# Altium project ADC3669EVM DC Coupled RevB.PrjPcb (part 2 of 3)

## Sheet ADC IO.SchDoc: ADC Input & Clock
size 431 x 279 mm; Date: Not shown in title block; ApprovedBy: Not shown in title block; CheckedBy: Not shown in title block; Author: Not shown in title block; CompanyName: Not shown in title block; Engineer: Not shown in title block; Organization: Not shown in title block; Address1: Not shown in title block; Address2: Not shown in title block; Address3: Not shown in title block; Address4: Not shown in title block; DocumentNumber: 1; Revision: Use project parameter SCH_Rev; SheetNumber: 8; SheetTotal: 17; PageSetup: Record=PageOptions¦CenterHorizontal=True¦CenterVertical=True¦PrintScale=1.00¦XCorrection=1.00¦YCorrection=1.00¦PrintKind=0¦BorderSize=5000000¦LeftOffset=0¦BottomOffset=0¦Orientation=2¦PaperLength=1000¦PaperWidth=1000¦Scale=100¦PaperSource=15¦PrintQuality=600¦MediaType=1¦DitherType=10¦PaperKind=Letter¦PrintScaleMode=1
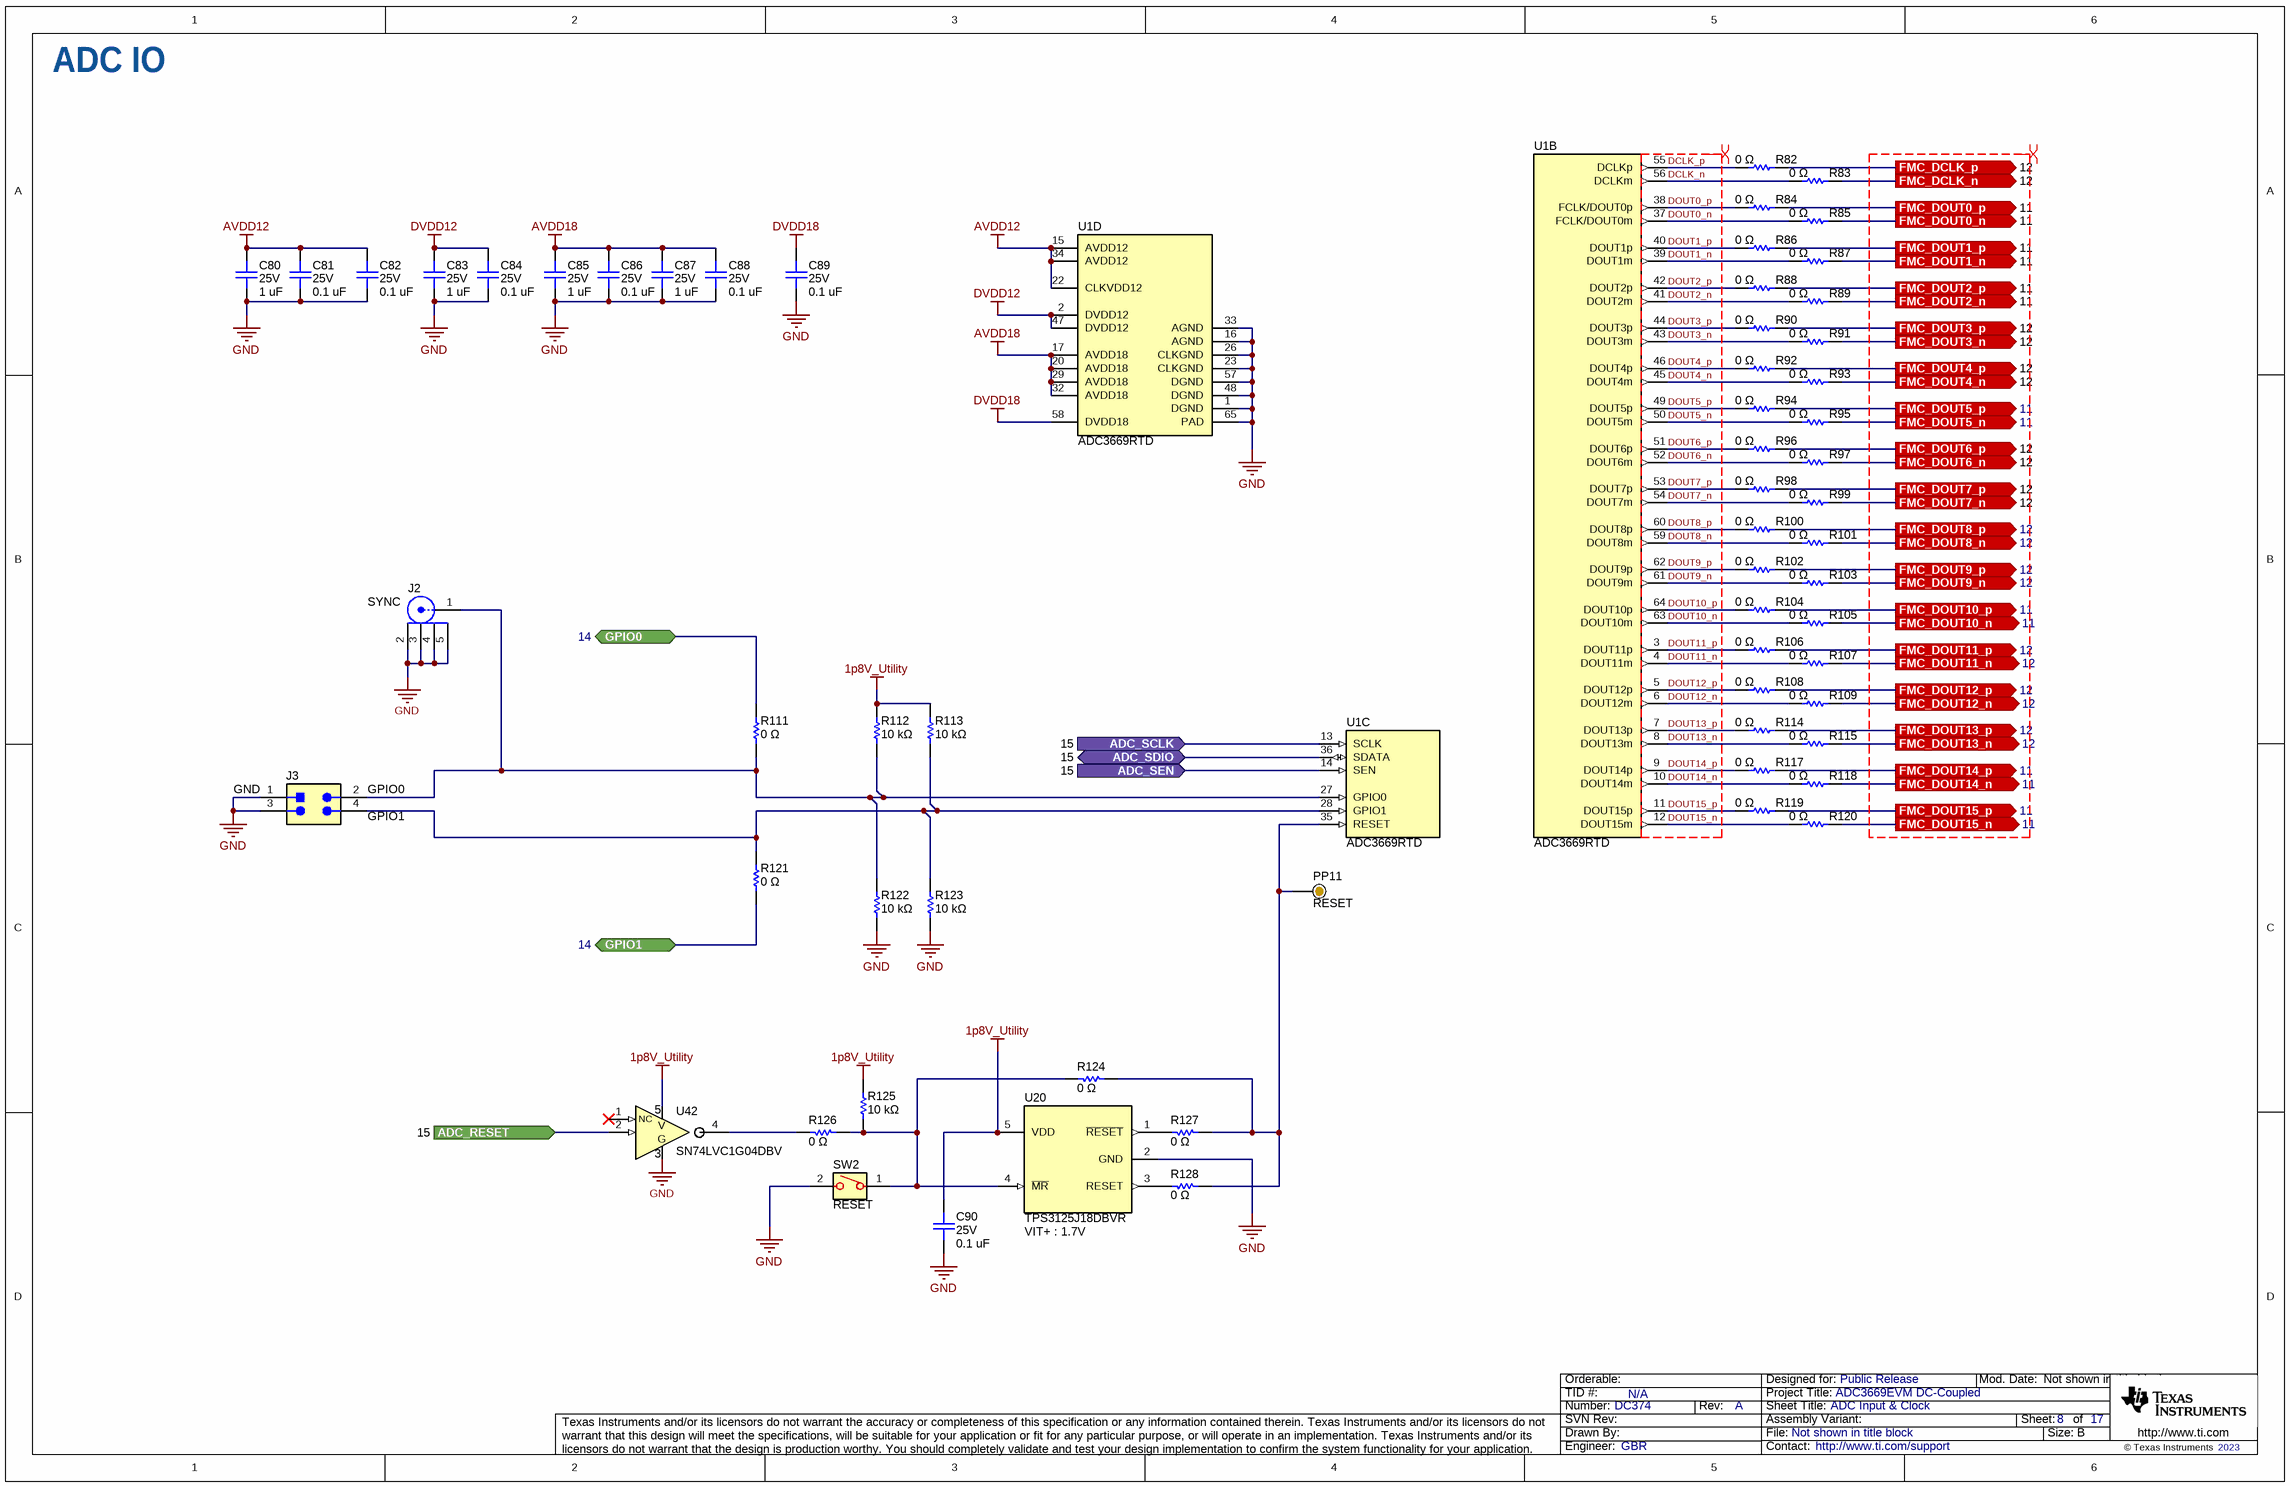
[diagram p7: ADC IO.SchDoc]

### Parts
C80  value 1 uF  Voltage - Rated: 25V  [0402L_cap]  (hidden comment: C1005X5R1E105K050BC)
C81  value 0.1 uF  Voltage - Rated: 25V  [0402L_cap]  (hidden comment: C1005X5R1E104K050BC)
C82  value 0.1 uF  Voltage - Rated: 25V  [0402L_cap]  (hidden comment: C1005X5R1E104K050BC)
C83  value 1 uF  Voltage - Rated: 25V  [0402L_cap]  (hidden comment: C1005X5R1E105K050BC)
C84  value 0.1 uF  Voltage - Rated: 25V  [0402L_cap]  (hidden comment: C1005X5R1E104K050BC)
C85  value 1 uF  Voltage - Rated: 25V  [0402L_cap]  (hidden comment: C1005X5R1E105K050BC)
C86  value 0.1 uF  Voltage - Rated: 25V  [0402L_cap]  (hidden comment: C1005X5R1E104K050BC)
C87  value 1 uF  Voltage - Rated: 25V  [0402L_cap]  (hidden comment: C1005X5R1E105K050BC)
C88  value 0.1 uF  Voltage - Rated: 25V  [0402L_cap]  (hidden comment: C1005X5R1E104K050BC)
C89  value 0.1 uF  Voltage - Rated: 25V  [0402L_cap]  (hidden comment: C1005X5R1E104K050BC)
C90  value 0.1 uF  Voltage - Rated: 25V  [0402L_cap]  (hidden comment: C1005X5R1E104K050BC)
J2  Text1: SYNC  [FP-132134-15_CONN_SMA_JACK-MFG]  (hidden comment: 132134-15)
J3  Text4: GPIO1  Text3: GND  Text2: GPIO0  [PBC02DAAN]  (hidden comment: TSW-102-14-S-D)
PP11  Text1: RESET  [ProbePoint_TH_40mil]  (hidden comment: Probe Point)  (no BOM)
R82  value 0 Ω  [0201]  (hidden comment: ERJ-1GN0R00C)
R83  value 0 Ω  [0201]  (hidden comment: ERJ-1GN0R00C)
R84  value 0 Ω  [0201]  (hidden comment: ERJ-1GN0R00C)
R85  value 0 Ω  [0201]  (hidden comment: ERJ-1GN0R00C)
R86  value 0 Ω  [0201]  (hidden comment: ERJ-1GN0R00C)
R87  value 0 Ω  [0201]  (hidden comment: ERJ-1GN0R00C)
R88  value 0 Ω  [0201]  (hidden comment: ERJ-1GN0R00C)
R89  value 0 Ω  [0201]  (hidden comment: ERJ-1GN0R00C)
R90  value 0 Ω  [0201]  (hidden comment: ERJ-1GN0R00C)
R91  value 0 Ω  [0201]  (hidden comment: ERJ-1GN0R00C)
R92  value 0 Ω  [0201]  (hidden comment: ERJ-1GN0R00C)
R93  value 0 Ω  [0201]  (hidden comment: ERJ-1GN0R00C)
R94  value 0 Ω  [0201]  (hidden comment: ERJ-1GN0R00C)
R95  value 0 Ω  [0201]  (hidden comment: ERJ-1GN0R00C)
R96  value 0 Ω  [0201]  (hidden comment: ERJ-1GN0R00C)
R97  value 0 Ω  [0201]  (hidden comment: ERJ-1GN0R00C)
R98  value 0 Ω  [0201]  (hidden comment: ERJ-1GN0R00C)
R99  value 0 Ω  [0201]  (hidden comment: ERJ-1GN0R00C)
R100  value 0 Ω  [0201]  (hidden comment: ERJ-1GN0R00C)
R101  value 0 Ω  [0201]  (hidden comment: ERJ-1GN0R00C)
R102  value 0 Ω  [0201]  (hidden comment: ERJ-1GN0R00C)
R103  value 0 Ω  [0201]  (hidden comment: ERJ-1GN0R00C)
R104  value 0 Ω  [0201]  (hidden comment: ERJ-1GN0R00C)
R105  value 0 Ω  [0201]  (hidden comment: ERJ-1GN0R00C)
R106  value 0 Ω  [0201]  (hidden comment: ERJ-1GN0R00C)
R107  value 0 Ω  [0201]  (hidden comment: ERJ-1GN0R00C)
R108  value 0 Ω  [0201]  (hidden comment: ERJ-1GN0R00C)
R109  value 0 Ω  [0201]  (hidden comment: ERJ-1GN0R00C)
R111  value 0 Ω  [0402L]  (hidden comment: ERJ-2GE0R00X)
R112  value 10 kΩ  [0402L]  (hidden comment: ERJ-PA2F1002X)
R113  value 10 kΩ  [0402L]  (hidden comment: ERJ-PA2F1002X)
R114  value 0 Ω  [0201]  (hidden comment: ERJ-1GN0R00C)
R115  value 0 Ω  [0201]  (hidden comment: ERJ-1GN0R00C)
R117  value 0 Ω  [0201]  (hidden comment: ERJ-1GN0R00C)
R118  value 0 Ω  [0201]  (hidden comment: ERJ-1GN0R00C)
R119  value 0 Ω  [0201]  (hidden comment: ERJ-1GN0R00C)
R120  value 0 Ω  [0201]  (hidden comment: ERJ-1GN0R00C)
R121  value 0 Ω  [0402L]  (hidden comment: ERJ-2GE0R00X)
R122  value 10 kΩ  [0402L]  (hidden comment: ERJ-PA2F1002X)
R123  value 10 kΩ  [0402L]  (hidden comment: ERJ-PA2F1002X)
R124  value 0 Ω  [0402L]  (hidden comment: ERJ-2GE0R00X)
R125  value 10 kΩ  [0402L]  (hidden comment: ERJ-2RKF1002X)
R126  value 0 Ω  [0402L]  (hidden comment: ERJ-2GE0R00X)
R127  value 0 Ω  [0402L]  (hidden comment: ERJ-2GE0R00X)
R128  value 0 Ω  [0402L]  (hidden comment: ERJ-2GE0R00X)
SW2  Text1: RESET  [FSMSM]  (hidden comment: FSMSM)
U1  ADC3669RTD  [RTD0064L]  (parts B,C,D of 4)
U20  TPS3125J18DBVR  Text1: VIT+ : 1.7V  [DBV0005A]
U42  SN74LVC1G04DBV  [DBV0005A]

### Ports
ADC_RESET (in, see 15), ADC_SCLK (in, see 15), ADC_SDIO (bidir, see 15), ADC_SEN (in, see 15), FMC_DCLK_n (out, see 12), FMC_DCLK_p (out, see 12), FMC_DOUT0_n (out, see 11), FMC_DOUT0_p (out, see 11), FMC_DOUT1_n (out, see 11), FMC_DOUT1_p (out, see 11), FMC_DOUT2_n (out, see 11), FMC_DOUT2_p (out, see 11), FMC_DOUT3_n (out, see 12), FMC_DOUT3_p (out, see 12), FMC_DOUT4_n (out, see 12), FMC_DOUT4_p (out, see 12), FMC_DOUT5_n (out, see 11), FMC_DOUT5_p (out, see 11), FMC_DOUT6_n (out, see 12), FMC_DOUT6_p (out, see 12), FMC_DOUT7_n (out, see 12), FMC_DOUT7_p (out, see 12), FMC_DOUT8_n (out, see 12), FMC_DOUT8_p (out, see 12), FMC_DOUT9_n (out, see 12), FMC_DOUT9_p (out, see 12), FMC_DOUT10_n (out, see 11), FMC_DOUT10_p (out, see 11), FMC_DOUT11_n (out, see 12), FMC_DOUT11_p (out, see 12), FMC_DOUT12_n (out, see 12), FMC_DOUT12_p (out, see 12), FMC_DOUT13_n (out, see 12), FMC_DOUT13_p (out, see 12), FMC_DOUT14_n (out, see 11), FMC_DOUT14_p (out, see 11), FMC_DOUT15_n (out, see 11), FMC_DOUT15_p (out, see 11), GPIO0 (bidir, see 14), GPIO1 (bidir, see 14)

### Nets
1p8V_Utility: C90.2 R112.1 R113.1 R125.2 U20.5(VDD) U42.5(VCC)
AVDD12: C80.2 C81.2 C82.2 U1.15(AVDD12) U1.22(CLKVDD12) U1.34(AVDD12)
AVDD18: C85.2 C86.2 C87.2 C88.2 U1.17(AVDD18) U1.20(AVDD18) U1.29(AVDD18) U1.32(AVDD18)
DVDD12: C83.2 C84.2 U1.2(DVDD12) U1.47(DVDD12)
DVDD18: C89.2 U1.58(DVDD18)
GND: C80.1 C81.1 C82.1 C83.1 C84.1 C85.1 C86.1 C87.1 C88.1 C89.1 C90.1 J2.2 J2.3 J2.4 J2.5 J3.1 J3.3 R122.2 R123.2 SW2.2 U1.1(DGND) U1.16(AGND) U1.23(CLKGND) U1.26(CLKGND) U1.33(AGND) U1.48(DGND) U1.57(DGND) U1.65(PAD) U20.2(GND) U42.3(GND)
ADC_RESET: U42.2(A) ; port ADC_RESET
ADC_SCLK: U1.13(SCLK) ; port ADC_SCLK
ADC_SDIO: U1.36(SDATA) ; port ADC_SDIO
ADC_SEN: U1.14(SEN) ; port ADC_SEN
DCLK_n: R83.1 U1.56(DCLKm)
DCLK_p: R82.1 U1.55(DCLKp)
DOUT0_n: R85.1 U1.37(FCLK/DOUT0m)
DOUT0_p: R84.1 U1.38(FCLK/DOUT0p)
DOUT1_n: R87.1 U1.39(DOUT1m)
DOUT1_p: R86.1 U1.40(DOUT1p)
DOUT2_n: R89.1 U1.41(DOUT2m)
DOUT2_p: R88.1 U1.42(DOUT2p)
DOUT3_n: R91.1 U1.43(DOUT3m)
DOUT3_p: R90.1 U1.44(DOUT3p)
DOUT4_n: R93.1 U1.45(DOUT4m)
DOUT4_p: R92.1 U1.46(DOUT4p)
DOUT5_n: R95.1 U1.50(DOUT5m)
DOUT5_p: R94.1 U1.49(DOUT5p)
DOUT6_n: R97.1 U1.52(DOUT6m)
DOUT6_p: R96.1 U1.51(DOUT6p)
DOUT7_n: R99.1 U1.54(DOUT7m)
DOUT7_p: R98.1 U1.53(DOUT7p)
DOUT8_n: R101.1 U1.59(DOUT8m)
DOUT8_p: R100.1 U1.60(DOUT8p)
DOUT9_n: R103.1 U1.61(DOUT9m)
DOUT9_p: R102.1 U1.62(DOUT9p)
DOUT10_n: R105.1 U1.63(DOUT10m)
DOUT10_p: R104.1 U1.64(DOUT10p)
DOUT11_n: R107.1 U1.4(DOUT11m)
DOUT11_p: R106.1 U1.3(DOUT11p)
DOUT12_n: R109.1 U1.6(DOUT12m)
DOUT12_p: R108.1 U1.5(DOUT12p)
DOUT13_n: R115.1 U1.8(DOUT13m)
DOUT13_p: R114.1 U1.7(DOUT13p)
DOUT14_n: R118.1 U1.10(DOUT14m)
DOUT14_p: R117.1 U1.9(DOUT14p)
DOUT15_n: R120.1 U1.12(DOUT15m)
DOUT15_p: R119.1 U1.11(DOUT15p)
FMC_DCLK_n: R83.2 ; port FMC_DCLK_n
FMC_DCLK_p: R82.2 ; port FMC_DCLK_p
FMC_DOUT0_n: R85.2 ; port FMC_DOUT0_n
FMC_DOUT0_p: R84.2 ; port FMC_DOUT0_p
FMC_DOUT1_n: R87.2 ; port FMC_DOUT1_n
FMC_DOUT1_p: R86.2 ; port FMC_DOUT1_p
FMC_DOUT2_n: R89.2 ; port FMC_DOUT2_n
FMC_DOUT2_p: R88.2 ; port FMC_DOUT2_p
FMC_DOUT3_n: R91.2 ; port FMC_DOUT3_n
FMC_DOUT3_p: R90.2 ; port FMC_DOUT3_p
FMC_DOUT4_n: R93.2 ; port FMC_DOUT4_n
FMC_DOUT4_p: R92.2 ; port FMC_DOUT4_p
FMC_DOUT5_n: R95.2 ; port FMC_DOUT5_n
FMC_DOUT5_p: R94.2 ; port FMC_DOUT5_p
FMC_DOUT6_n: R97.2 ; port FMC_DOUT6_n
FMC_DOUT6_p: R96.2 ; port FMC_DOUT6_p
FMC_DOUT7_n: R99.2 ; port FMC_DOUT7_n
FMC_DOUT7_p: R98.2 ; port FMC_DOUT7_p
FMC_DOUT8_n: R101.2 ; port FMC_DOUT8_n
FMC_DOUT8_p: R100.2 ; port FMC_DOUT8_p
FMC_DOUT9_n: R103.2 ; port FMC_DOUT9_n
FMC_DOUT9_p: R102.2 ; port FMC_DOUT9_p
FMC_DOUT10_n: R105.2 ; port FMC_DOUT10_n
FMC_DOUT10_p: R104.2 ; port FMC_DOUT10_p
FMC_DOUT11_n: R107.2 ; port FMC_DOUT11_n
FMC_DOUT11_p: R106.2 ; port FMC_DOUT11_p
FMC_DOUT12_n: R109.2 ; port FMC_DOUT12_n
FMC_DOUT12_p: R108.2 ; port FMC_DOUT12_p
FMC_DOUT13_n: R115.2 ; port FMC_DOUT13_n
FMC_DOUT13_p: R114.2 ; port FMC_DOUT13_p
FMC_DOUT14_n: R118.2 ; port FMC_DOUT14_n
FMC_DOUT14_p: R117.2 ; port FMC_DOUT14_p
FMC_DOUT15_n: R120.2 ; port FMC_DOUT15_n
FMC_DOUT15_p: R119.2 ; port FMC_DOUT15_p
GPIO0: R111.2 ; port GPIO0
GPIO1: R121.1 ; port GPIO1
NetJ2_1: J2.1 J3.2 R111.1 R112.2 R122.1 U1.27(GPIO0)
NetJ3_4: J3.4 R113.2 R121.2 R123.1 U1.28(GPIO1)
NetPP11_1: PP11.1 R124.1 R127.1 R128.1 U1.35(RESET)
NetR124_2: R124.2 R125.1 R126.1 SW2.1 U20.4(~{MR})
NetR126_2: R126.2 U42.4(Y)
NetR127_2: R127.2 U20.1(~{RESET})
NetR128_2: R128.2 U20.3(RESET)

Not connected (* = marked no-connect by the designer): U42 1(NC)*

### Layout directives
differential pair; net class SERDES: (no net found under the mark)
differential pair: DCLK_n, DCLK_p, DOUT0_n, DOUT0_p, DOUT1_n, DOUT1_p, DOUT2_n, DOUT2_p, DOUT3_n, DOUT3_p, DOUT4_n, DOUT4_p, DOUT5_n, DOUT5_p, DOUT6_n, DOUT6_p, DOUT7_n, DOUT7_p, DOUT8_n, DOUT8_p, DOUT9_n, DOUT9_p, DOUT10_n, DOUT10_p, DOUT11_n, DOUT11_p, DOUT12_n, DOUT12_p, DOUT13_n, DOUT13_p, DOUT14_n, DOUT14_p, DOUT15_n, DOUT15_p

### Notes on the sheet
- ADC IO

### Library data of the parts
C80 C83 C85 C87 = capcc02750: CAP CER 1UF 25V X5R 0402; Manufacturer: TDK Corporation; CompType: Capacitor Ceramic; Tolerance: ±10%; SizeX_mm: 1; SizeY_mm: 0.5; SizeZ_mm: 0.55
C81 C82 C84 C86 C88-C90 = capcc01263: CAP CER 0.1UF 25V X5R 0402; Manufacturer: TDK Corporation; CompType: Capacitor Ceramic; Tolerance: ±10%; SizeX_mm: 1; SizeY_mm: 0.5; SizeZ_mm: 0.55
J2 = 132134-15: SMA Connector Jack, Female Socket 50Ohm Surface Mount, Through Hole Solder; Manufacturer: Amphenol RF; UniqueID: cmp00028; CompType: RF Connector
J3 = TSW-102-14-S-D: Header, 100mil, 2x2, Gold, TH; Manufacturer: Samtec; Alt Manufacturer: Sullins Connector Solutions; UniqueID: cmp00018; Pitch (mm): 2.54
PP11 = cmp00025: Probe Point that can be used in lue of a test point
R82-R109 R114 R115 R117-R120 = RSMD020101699: RES SMD 0 OHM JUMPER 1/20W 0201; Manufacturer: Panasonic Electronic Components; CompType: Resistor SMD; Power (Watts): 0.05W, 1/20W
R111 R121 R124 R126-R128 = RSMD040200001: RES SMD 0 OHM JUMPER 1/10W 0402; Manufacturer: Panasonic Electronic Components; CompType: Resistor SMD; Power (Watts): 0.1W, 1/10W; SizeX_mm: 1; SizeY_mm: 0.5; SizeZ_mm: 0.4
R112 R113 R122 R123 = RSMD040200311: RES SMD 10K OHM 1% 1/5W 0402; Manufacturer: Panasonic Electronic Components; CompType: Resistor SMD; Power (Watts): 0.2W, 1/5W; Temperature Coefficient: ±100ppm/°C; SizeX_mm: 1; SizeY_mm: 0.5; SizeZ_mm: 0.4
R125 = RSMD040200314: RES SMD 10K OHM 1% 1/10W 0402; Manufacturer: Panasonic Electronic Components; CompType: Resistor SMD; Power (Watts): 0.1W, 1/10W; Temperature Coefficient: ±100ppm/°C; SizeX_mm: 1; SizeY_mm: 0.5; SizeZ_mm: 0.4
SW2 = cmp00234: SWITCH TACTILE SPST-NO 0.05A 24V; Manufacturer: TE Connectivity; CompType: Push Button
U1 = cmp00321: 16-Bit 500-MSPS Analog-to-Digital Converter; Manufacturer: Texas Instruments; CompType: ADC
U20 = cmp00229: Push-pull, supply voltage supervisor with manual reset; Manufacturer: Texas Instruments; Alt PartNumber: TPS3125J18DBVT; CompType: Voltage Detector
U42 = SN74LVC1G04DBV: Single 1.65-V to 5.5-V inverter; Manufacturer: Texas Instruments

## Sheet ADC Analog Input.SchDoc
size 431 x 279 mm; Date: Not shown in title block; ApprovedBy: Not shown in title block; CheckedBy: Not shown in title block; Author: Not shown in title block; CompanyName: Not shown in title block; Engineer: Not shown in title block; Organization: Not shown in title block; Address1: Not shown in title block; Address2: Not shown in title block; Address3: Not shown in title block; Address4: Not shown in title block; DocumentNumber: 1; Revision: Use project parameter SCH_Rev; SheetNumber: 9; SheetTotal: 17; PageSetup: Record=PageOptions¦CenterHorizontal=True¦CenterVertical=True¦PrintScale=1.00¦XCorrection=1.00¦YCorrection=1.00¦PrintKind=0¦BorderSize=5000000¦LeftOffset=0¦BottomOffset=0¦Orientation=2¦PaperLength=1000¦PaperWidth=1000¦Scale=100¦PaperSource=15¦PrintQuality=600¦MediaType=1¦DitherType=10¦PaperKind=Letter¦PrintScaleMode=1
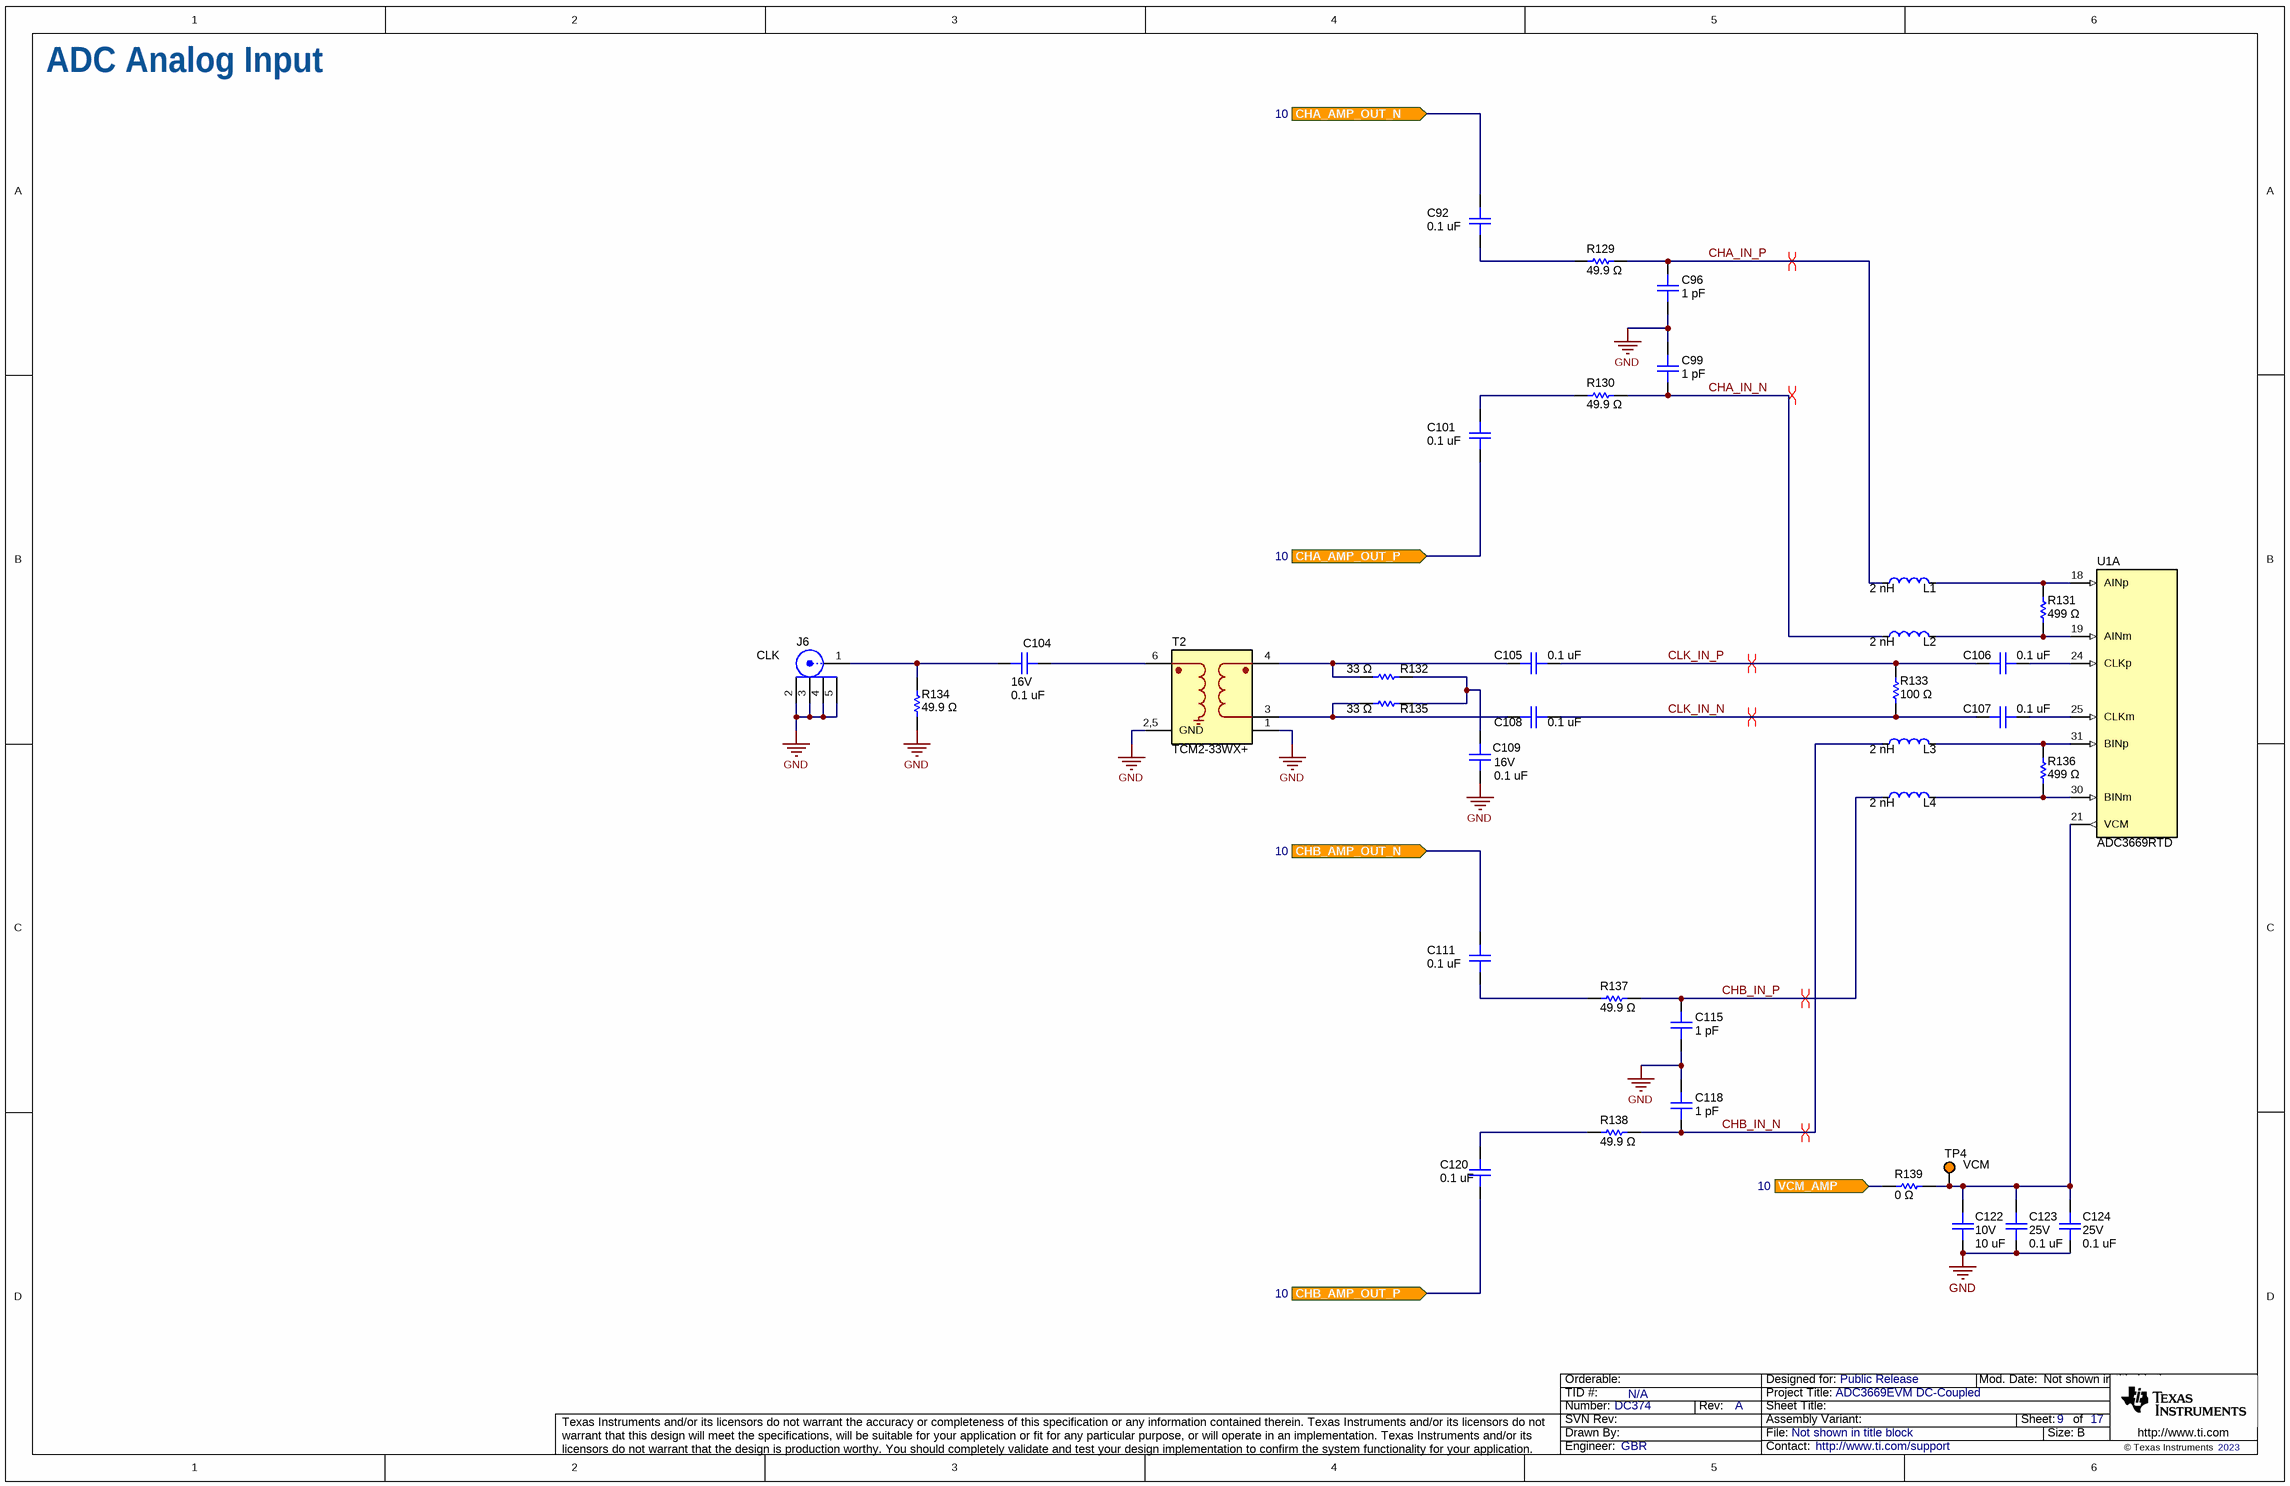
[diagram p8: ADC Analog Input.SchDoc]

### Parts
C92  value 0.1 uF  [0201_cap]  (hidden comment: GRM033Z71C104KE14D)
C96  value 1 pF  [0201_cap]  (hidden comment: 02015J1R0PBSTR)
C99  value 1 pF  [0201_cap]  (hidden comment: 02015J1R0PBSTR)
C101  value 0.1 uF  [0201_cap]  (hidden comment: GRM033Z71C104KE14D)
C104  value 0.1 uF  Voltage - Rated: 16V  [0201_cap]  (hidden comment: GRM033Z71C104KE14D)
C105  value 0.1 uF  [0201_cap]  (hidden comment: GRM033Z71C104KE14D)
C106  value 0.1 uF  [0201_cap]  (hidden comment: GRM033Z71C104KE14D)
C107  value 0.1 uF  [0201_cap]  (hidden comment: GRM033Z71C104KE14D)
C108  value 0.1 uF  [0201_cap]  (hidden comment: GRM033Z71C104KE14D)
C109  value 0.1 uF  Voltage - Rated: 16V  [0201_cap]  (hidden comment: GRM033Z71C104KE14D)
C111  value 0.1 uF  [0201_cap]  (hidden comment: GRM033Z71C104KE14D)
C115  value 1 pF  [0201_cap]  (hidden comment: 02015J1R0PBSTR)
C118  value 1 pF  [0201_cap]  (hidden comment: 02015J1R0PBSTR)
C120  value 0.1 uF  [0201_cap]  (hidden comment: GRM033Z71C104KE14D)
C122  value 10 uF  Voltage - Rated: 10V  [0402L_cap]  (hidden comment: 0402ZD106MAT2A)
C123  value 0.1 uF  Voltage - Rated: 25V  [0402L_cap]  (hidden comment: C1005X5R1E104K050BC)
C124  value 0.1 uF  Voltage - Rated: 25V  [0402L_cap]  (hidden comment: C1005X5R1E104K050BC)
J6  Text1: CLK  [FP-132134-15_CONN_SMA_JACK-MFG]  (hidden comment: 132134-15)
L1  value 2 nH  [0201]  (hidden comment: LQP03HQ2N0B02D)
L2  value 2 nH  [0201]  (hidden comment: LQP03HQ2N0B02D)
L3  value 2 nH  [0201]  (hidden comment: LQP03HQ2N0B02D)
L4  value 2 nH  [0201]  (hidden comment: LQP03HQ2N0B02D)
R129  value 49.9 Ω  [0201]  (hidden comment: ERJ-U01F49R9C)
R130  value 49.9 Ω  [0201]  (hidden comment: ERJ-U01F49R9C)
R131  value 499 Ω  [0201]  (hidden comment: ERJ-1GNF4990C)
R132  value 33 Ω  [0201]  (hidden comment: ERJ-1GNF33R0C)
R133  value 100 Ω  [0201]  (hidden comment: ERJ-1GNF1000C)
R134  value 49.9 Ω  [0201]  (hidden comment: ERJ-U01F49R9C)
R135  value 33 Ω  [0201]  (hidden comment: ERJ-1GNF33R0C)
R136  value 499 Ω  [0201]  (hidden comment: ERJ-1GNF4990C)
R137  value 49.9 Ω  [0201]  (hidden comment: ERJ-U01F49R9C)
R138  value 49.9 Ω  [0201]  (hidden comment: ERJ-U01F49R9C)
R139  value 0 Ω  [0402L]  (hidden comment: ERJ-2GE0R00X)
T2  TCM2-33WX+  [DB1627 - Vias 1,2,5]
TP4  Text1: VCM  [Keystone5013]  (hidden comment: cmp00043)
U1  ADC3669RTD  [RTD0064L]  (part A of 4)

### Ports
CHA_AMP_OUT_N (in, see 10), CHA_AMP_OUT_P (in, see 10), CHB_AMP_OUT_N (in, see 10), CHB_AMP_OUT_P (in, see 10), VCM_AMP (in, see 10)

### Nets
GND: C96.1 C99.2 C109.1 C115.1 C118.2 C122.1 C123.1 C124.1 J6.2 J6.3 J6.4 J6.5 R134.1 T2.1 T2.2,5(GND)
CHA_AMP_OUT_N: C92.1 ; port CHA_AMP_OUT_N
CHA_AMP_OUT_P: C101.2 ; port CHA_AMP_OUT_P
CHA_IN_N: C99.1 L2.1 R130.2
CHA_IN_P: C96.2 L1.1 R129.2
CHB_AMP_OUT_N: C111.2 ; port CHB_AMP_OUT_N
CHB_AMP_OUT_P: C120.1 ; port CHB_AMP_OUT_P
CHB_IN_N: C118.1 L3.1 R138.2
CHB_IN_P: C115.2 L4.1 R137.2
CLK_IN_N: C107.1 C108.2 R133.1
CLK_IN_P: C105.2 C106.1 R133.2
VCM_AMP: R139.2 ; port VCM_AMP
NetC92_2: C92.2 R129.1
NetC101_1: C101.1 R130.1
NetC104_1: C104.1 J6.1 R134.2
NetC104_2: C104.2 T2.6(Primary_Dot)
NetC105_1: C105.1 R132.2 T2.4(Secondary_Dot)
NetC106_2: C106.2 U1.24(CLKp)
NetC107_2: C107.2 U1.25(CLKm)
NetC108_1: C108.1 R135.2 T2.3
NetC109_2: C109.2 R132.1 R135.1
NetC111_1: C111.1 R137.1
NetC120_2: C120.2 R138.1
NetC122_2: C122.2 C123.2 C124.2 R139.1 TP4.1 U1.21(VCM)
NetL1_2: L1.2 R131.2 U1.18(AINp)
NetL2_2: L2.2 R131.1 U1.19(AINm)
NetL3_2: L3.2 R136.2 U1.31(BINp)
NetL4_2: L4.2 R136.1 U1.30(BINm)

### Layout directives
differential pair: CHA_IN_N, CHA_IN_P, CHB_IN_N, CHB_IN_P, CLK_IN_N, CLK_IN_P

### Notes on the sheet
- ADC Analog Input

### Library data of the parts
C92 C101 C104-C109 C111 C120 = capcc09263: CAP CER 0.1UF 16V X7R 0201; Manufacturer: Murata Electronics; SizeZ_mm: 0.33; SizeY_mm: 0.3; CompType: Capacitor Ceramic; SizeX_mm: 0.6; Tolerance: ±10%
C96 C99 C115 C118 = 0201RFCaps0738: CAP THIN FILM 1PF 50V 0201; Manufacturer: KYOCERA AVX; CompType: Capactior RF; Tolerance: ±0.02pF; SizeX_mm: 0.58; SizeY_mm: 0.3; SizeZ_mm: 0.33
C122 = capcc09406: CAP CER 10UF 10V X5R 0402; Manufacturer: KYOCERA AVX; CompType: Capacitor Ceramic; Tolerance: ±20%; SizeX_mm: 1; SizeY_mm: 0.5; SizeZ_mm: 0.7
C123 C124 = capcc01263: as C81 on sheet ADC IO
J6 = 132134-15: as J2 on sheet ADC IO
L1-L4 = indrf00113: FIXED IND 2NH 600MA 120MOHM SMD; Manufacturer: Murata Electronics; CompType: Inductor RF; Tolerance: ±0.1nH; Material: Non-Magnetic; DC Resistance (DCR): 120mOhm Max; Q @ Freq: 20 @ 500MHz; Frequency - Self Resonant: 9GHz; SizeX_mm: 0.76; SizeY_mm: 0.33; SizeZ_mm: 0.55
R129 R130 R134 R137 R138 = RSMD020100423: RES 49.9 OHM 1% 1/20W 0201 SMD; Manufacturer: Panasonic Electronic Components; CompType: Resistor SMD; Power (Watts): 0.05W, 1/20W; Temperature Coefficient: ±200ppm/°C
R131 R136 = RSMD020100201: RES SMD 499 OHM 1% 1/20W 0201; Manufacturer: Panasonic Electronic Components; CompType: Resistor SMD; Power (Watts): 0.05W, 1/20W; Temperature Coefficient: ±200ppm/°C
R132 R135 = RSMD020100013: RES SMD 33 OHM 1% 1/20W 0201; Manufacturer: Panasonic Electronic Components; CompType: Resistor SMD; Power (Watts): 0.05W, 1/20W; Temperature Coefficient: ±200ppm/°C
R133 = RSMD020100289: RES SMD 100 OHM 1% 1/20W 0201; Manufacturer: Panasonic Electronic Components; CompType: Resistor SMD; Power (Watts): 0.05W, 1/20W; Temperature Coefficient: ±200ppm/°C
R139 = RSMD040200001: as R111 on sheet ADC IO
T2 = TCM2-33WX+: 1:2 CORE & WIRE Transformer, 10 to 3000 MHz, 50Ω; Manufacturer: Mini-Circuits; CompType: Balun; UniqueID: cmp00349
TP4 = cmp00043: Test Point, Multipurpose, Orange, TH; PartNumber: 5013; Manufacturer: Keystone
U1 = cmp00321: as U1 on sheet ADC IO

## Sheet Amplifier.SchDoc
size 431 x 279 mm; Date: Not shown in title block; ApprovedBy: Not shown in title block; CheckedBy: Not shown in title block; Author: Not shown in title block; CompanyName: Not shown in title block; Engineer: Not shown in title block; Organization: Not shown in title block; Address1: Not shown in title block; Address2: Not shown in title block; Address3: Not shown in title block; Address4: Not shown in title block; DocumentNumber: 1; Revision: Use project parameter SCH_Rev; SheetNumber: 10; SheetTotal: 17; PageSetup: Record=PageOptions¦CenterHorizontal=True¦CenterVertical=True¦PrintScale=1.00¦XCorrection=1.00¦YCorrection=1.00¦PrintKind=0¦BorderSize=5000000¦LeftOffset=0¦BottomOffset=0¦Orientation=2¦PaperLength=1000¦PaperWidth=1000¦Scale=100¦PaperSource=15¦PrintQuality=600¦MediaType=1¦DitherType=10¦PaperKind=Letter¦PrintScaleMode=1
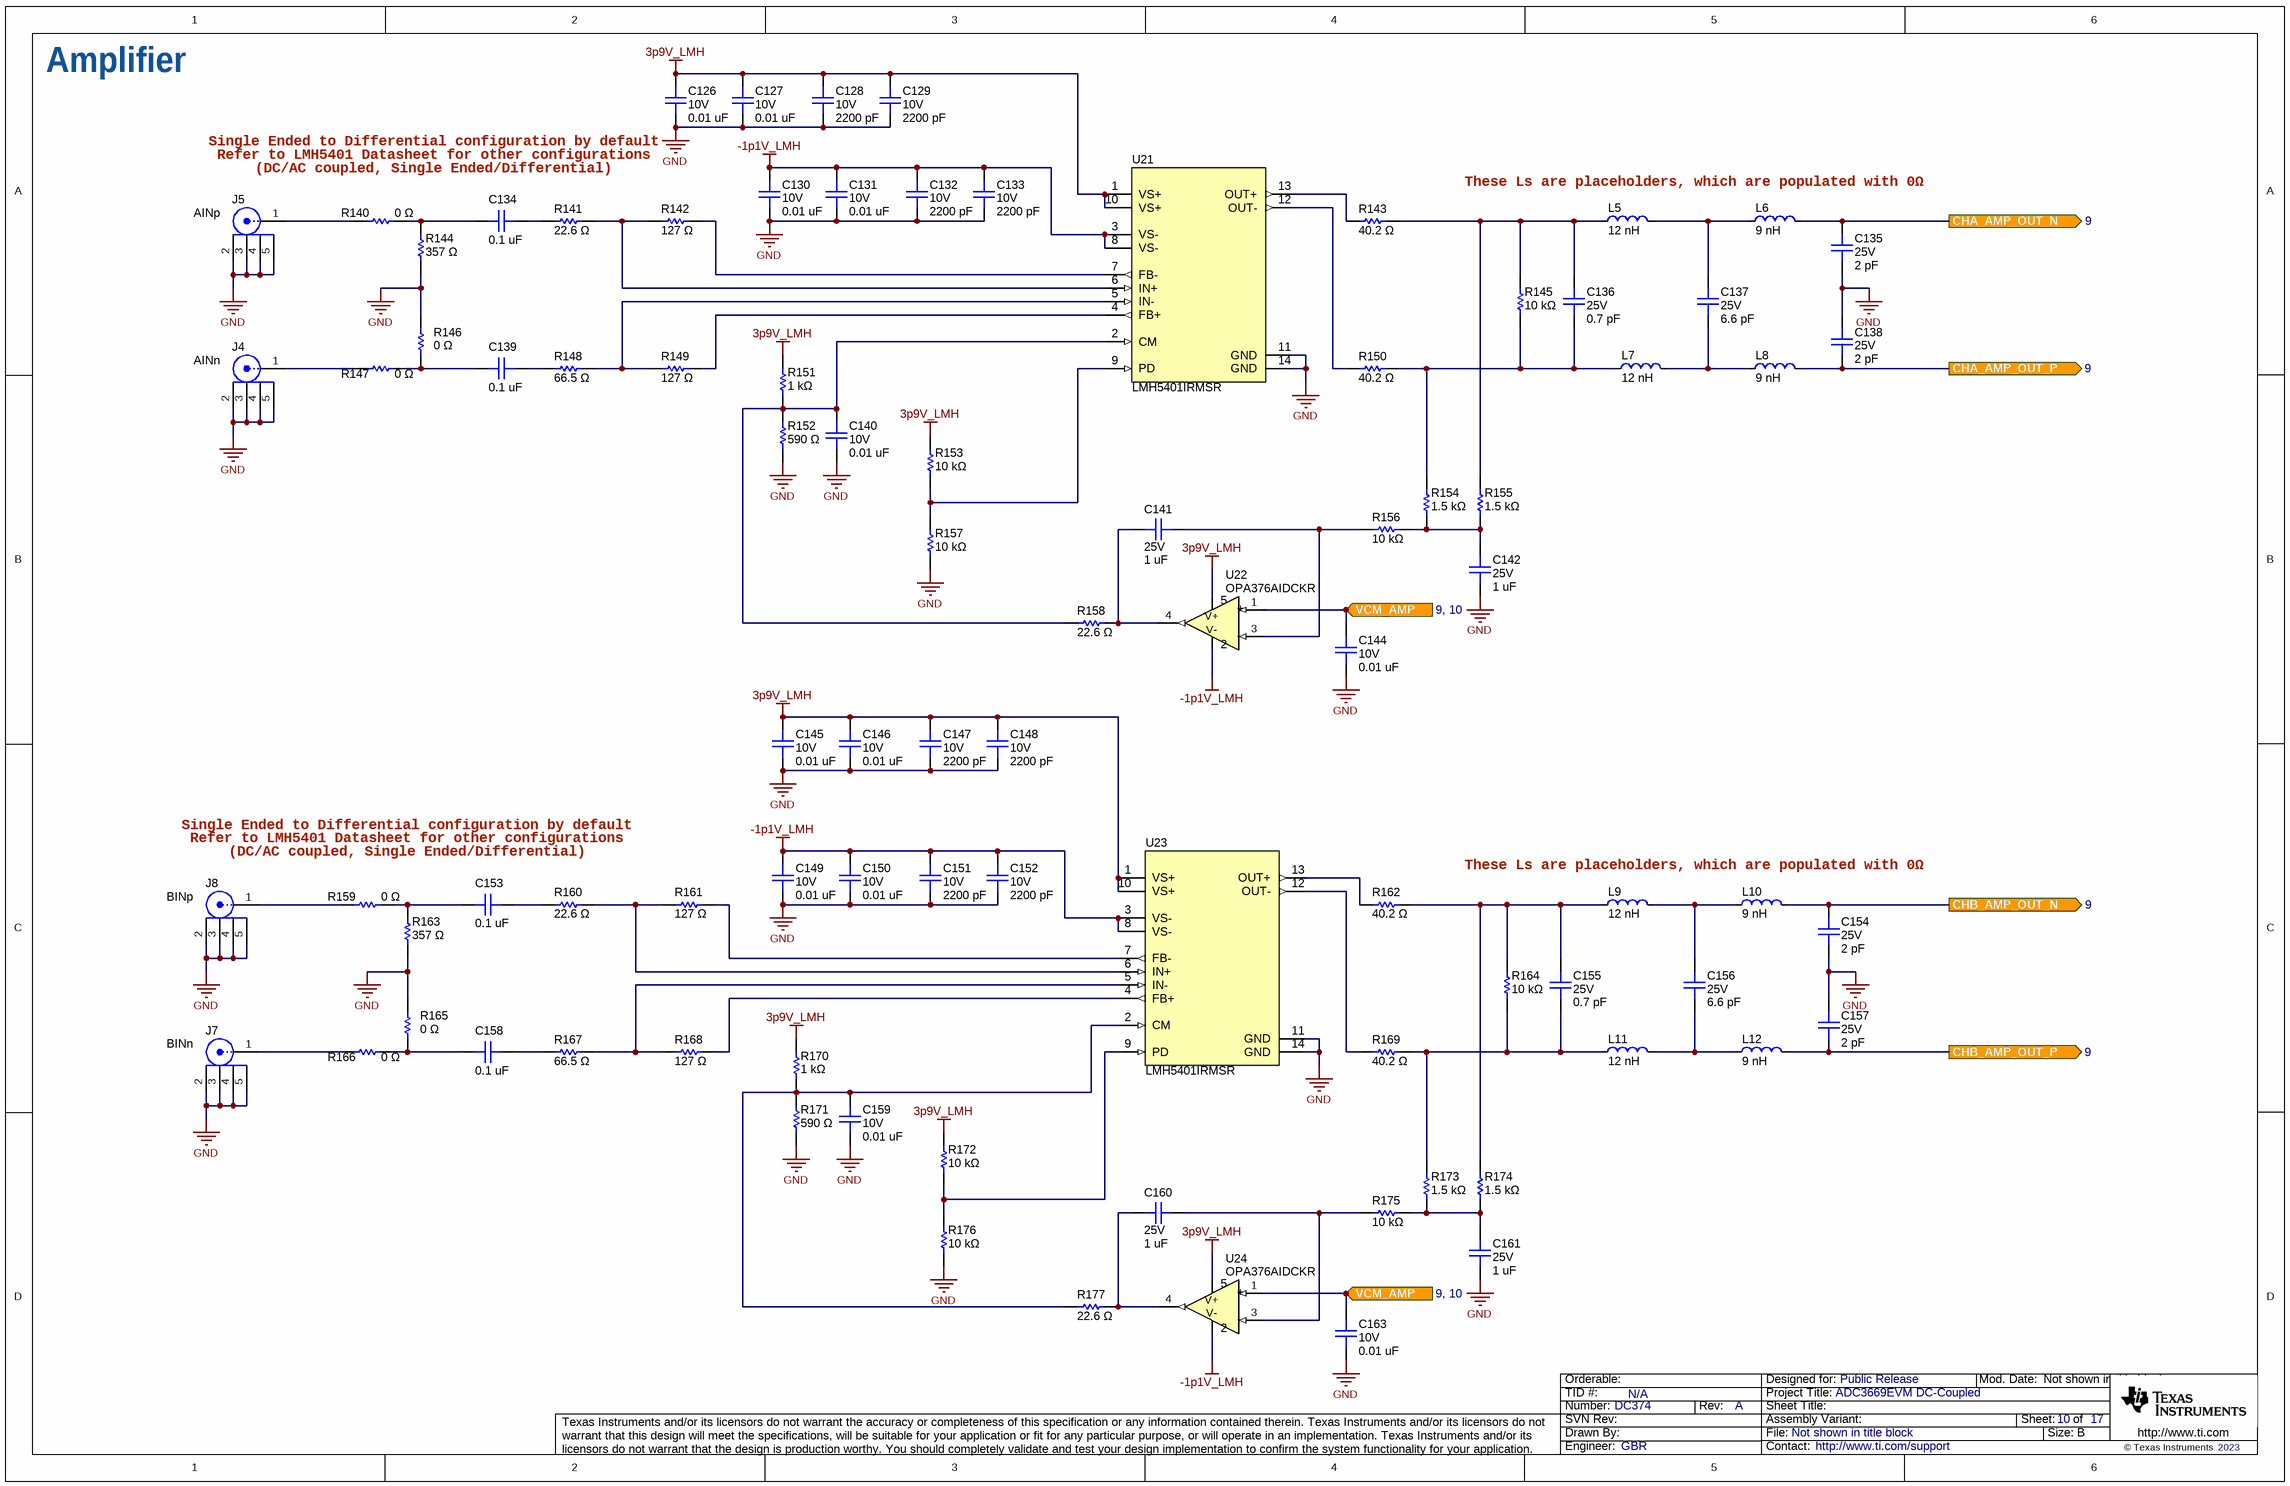
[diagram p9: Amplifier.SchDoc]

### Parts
C126  value 0.01 uF  Voltage - Rated: 10V  [0201_cap]  (hidden comment: CGA1A2X7R1A103K030BA)
C127  value 0.01 uF  Voltage - Rated: 10V  [0201_cap]  (hidden comment: CGA1A2X7R1A103K030BA)
C128  value 2200 pF  Voltage - Rated: 10V  [0201_cap]  (hidden comment: 0201ZC222KAT2A)
C129  value 2200 pF  Voltage - Rated: 10V  [0201_cap]  (hidden comment: 0201ZC222KAT2A)
C130  value 0.01 uF  Voltage - Rated: 10V  [0201_cap]  (hidden comment: CGA1A2X7R1A103K030BA)
C131  value 0.01 uF  Voltage - Rated: 10V  [0201_cap]  (hidden comment: CGA1A2X7R1A103K030BA)
C132  value 2200 pF  Voltage - Rated: 10V  [0201_cap]  (hidden comment: 0201ZC222KAT2A)
C133  value 2200 pF  Voltage - Rated: 10V  [0201_cap]  (hidden comment: 0201ZC222KAT2A)
C134  value 0.1 uF  [0201_cap]  (hidden comment: GRM033Z71C104KE14D)
C135  value 2 pF  Voltage - Rated: 25V  [0201_cap]  (hidden comment: GJM0335C1E2R0WB01D)
C136  value 0.7 pF  Voltage - Rated: 25V  [0201_cap]  (hidden comment: GJM0335C1ER70BB01J)
C137  value 6.6 pF  Voltage - Rated: 25V  [0201_cap]  (hidden comment: GJM0335C1E6R6CB01D)
C138  value 2 pF  Voltage - Rated: 25V  [0201_cap]  (hidden comment: GJM0335C1E2R0WB01D)
C139  value 0.1 uF  [0201_cap]  (hidden comment: GRM033Z71C104KE14D)
C140  value 0.01 uF  Voltage - Rated: 10V  [0201_cap]  (hidden comment: CGA1A2X7R1A103K030BA)
C141  value 1 uF  Voltage - Rated: 25V  [0402L_cap]  (hidden comment: C1005X5R1E105K050BC)
C142  value 1 uF  Voltage - Rated: 25V  [0402L_cap]  (hidden comment: C1005X5R1E105K050BC)
C144  value 0.01 uF  Voltage - Rated: 10V  [0201_cap]  (hidden comment: CGA1A2X7R1A103K030BA)
C145  value 0.01 uF  Voltage - Rated: 10V  [0201_cap]  (hidden comment: CGA1A2X7R1A103K030BA)
C146  value 0.01 uF  Voltage - Rated: 10V  [0201_cap]  (hidden comment: CGA1A2X7R1A103K030BA)
C147  value 2200 pF  Voltage - Rated: 10V  [0201_cap]  (hidden comment: 0201ZC222KAT2A)
C148  value 2200 pF  Voltage - Rated: 10V  [0201_cap]  (hidden comment: 0201ZC222KAT2A)
C149  value 0.01 uF  Voltage - Rated: 10V  [0201_cap]  (hidden comment: CGA1A2X7R1A103K030BA)
C150  value 0.01 uF  Voltage - Rated: 10V  [0201_cap]  (hidden comment: CGA1A2X7R1A103K030BA)
C151  value 2200 pF  Voltage - Rated: 10V  [0201_cap]  (hidden comment: 0201ZC222KAT2A)
C152  value 2200 pF  Voltage - Rated: 10V  [0201_cap]  (hidden comment: 0201ZC222KAT2A)
C153  value 0.1 uF  [0201_cap]  (hidden comment: GRM033Z71C104KE14D)
C154  value 2 pF  Voltage - Rated: 25V  [0201_cap]  (hidden comment: GJM0335C1E2R0WB01D)
C155  value 0.7 pF  Voltage - Rated: 25V  [0201_cap]  (hidden comment: GJM0335C1ER70BB01J)
C156  value 6.6 pF  Voltage - Rated: 25V  [0201_cap]  (hidden comment: GJM0335C1E6R6CB01D)
C157  value 2 pF  Voltage - Rated: 25V  [0201_cap]  (hidden comment: GJM0335C1E2R0WB01D)
C158  value 0.1 uF  [0201_cap]  (hidden comment: GRM033Z71C104KE14D)
C159  value 0.01 uF  Voltage - Rated: 10V  [0201_cap]  (hidden comment: CGA1A2X7R1A103K030BA)
C160  value 1 uF  Voltage - Rated: 25V  [0402L_cap]  (hidden comment: C1005X5R1E105K050BC)
C161  value 1 uF  Voltage - Rated: 25V  [0402L_cap]  (hidden comment: C1005X5R1E105K050BC)
C163  value 0.01 uF  Voltage - Rated: 10V  [0201_cap]  (hidden comment: CGA1A2X7R1A103K030BA)
J4  Text1: AINn  [FP-132134-15_CONN_SMA_JACK-MFG]  (hidden comment: 132134-15)
J5  Text1: AINp  [FP-132134-15_CONN_SMA_JACK-MFG]  (hidden comment: 132134-15)
J7  Text1: BINn  [FP-132134-15_CONN_SMA_JACK-MFG]  (hidden comment: 132134-15)
J8  Text1: BINp  [FP-132134-15_CONN_SMA_JACK-MFG]  (hidden comment: 132134-15)
L5  value 12 nH  [026011C]  (hidden comment: 026011C-12NXJRU)
L6  value 9 nH  [026011C]  (hidden comment: 026011C-9N0XJRU)
L7  value 12 nH  [026011C]  (hidden comment: 026011C-12NXJRU)
L8  value 9 nH  [026011C]  (hidden comment: 026011C-9N0XJRU)
L9  value 12 nH  [026011C]  (hidden comment: 026011C-12NXJRU)
L10  value 9 nH  [026011C]  (hidden comment: 026011C-9N0XJRU)
L11  value 12 nH  [026011C]  (hidden comment: 026011C-12NXJRU)
L12  value 9 nH  [026011C]  (hidden comment: 026011C-9N0XJRU)
R140  value 0 Ω  [0201]  (hidden comment: ERJ-1GN0R00C)
R141  value 22.6 Ω  [0201]  (hidden comment: ERJ-U01F22R6C)
R142  value 127 Ω  [0201]  (hidden comment: ERJ-1GNF1270C)
R143  value 40.2 Ω  [0201]  (hidden comment: ERJ-1GNF40R2C)
R144  value 357 Ω  [0201]  (hidden comment: ERJ-1GNF3570C)
R145  value 10 kΩ  [0201]  (hidden comment: ERJ-U01F1002C)
R146  value 0 Ω  [0201]  (hidden comment: ERJ-1GN0R00C)
R147  value 0 Ω  [0201]  (hidden comment: ERJ-1GN0R00C)
R148  value 66.5 Ω  [0201]  (hidden comment: ERJ-1GNF66R5C)
R149  value 127 Ω  [0201]  (hidden comment: ERJ-1GNF1270C)
R150  value 40.2 Ω  [0201]  (hidden comment: ERJ-1GNF40R2C)
R151  value 1 kΩ  [0402L]  (hidden comment: ERJ-2GEJ102X)
R152  value 590 Ω  [0402L]  (hidden comment: ERJ-2RKF5900X)
R153  value 10 kΩ  [0402L]  (hidden comment: ERJ-2RKF1002X)
R154  value 1.5 kΩ  [0201]  (hidden comment: ERJ-U01F1501C)
R155  value 1.5 kΩ  [0201]  (hidden comment: ERJ-U01F1501C)
R156  value 10 kΩ  [0201]  (hidden comment: ERJ-U01F1002C)
R157  value 10 kΩ  [0402L]  (hidden comment: ERJ-PA2F1002X)
R158  value 22.6 Ω  [0201]  (hidden comment: ERJ-U01F22R6C)
R159  value 0 Ω  [0201]  (hidden comment: ERJ-1GN0R00C)
R160  value 22.6 Ω  [0201]  (hidden comment: ERJ-U01F22R6C)
R161  value 127 Ω  [0201]  (hidden comment: ERJ-1GNF1270C)
R162  value 40.2 Ω  [0201]  (hidden comment: ERJ-1GNF40R2C)
R163  value 357 Ω  [0201]  (hidden comment: ERJ-1GNF3570C)
R164  value 10 kΩ  [0201]  (hidden comment: ERJ-U01F1002C)
R165  value 0 Ω  [0201]  (hidden comment: ERJ-1GN0R00C)
R166  value 0 Ω  [0201]  (hidden comment: ERJ-1GN0R00C)
R167  value 66.5 Ω  [0201]  (hidden comment: ERJ-1GNF66R5C)
R168  value 127 Ω  [0201]  (hidden comment: ERJ-1GNF1270C)
R169  value 40.2 Ω  [0201]  (hidden comment: ERJ-1GNF40R2C)
R170  value 1 kΩ  [0402L]  (hidden comment: ERJ-2GEJ102X)
R171  value 590 Ω  [0402L]  (hidden comment: ERJ-2RKF5900X)
R172  value 10 kΩ  [0402L]  (hidden comment: ERJ-2RKF1002X)
R173  value 1.5 kΩ  [0201]  (hidden comment: ERJ-U01F1501C)
R174  value 1.5 kΩ  [0201]  (hidden comment: ERJ-U01F1501C)
R175  value 10 kΩ  [0201]  (hidden comment: ERJ-U01F1002C)
R176  value 10 kΩ  [0402L]  (hidden comment: ERJ-PA2F1002X)
R177  value 22.6 Ω  [0201]  (hidden comment: ERJ-U01F22R6C)
U21  LMH5401IRMSR  [RMS0014A]
U22  OPA376AIDCKR  [DCK0005A]
U23  LMH5401IRMSR  [RMS0014A]
U24  OPA376AIDCKR  [DCK0005A]

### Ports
CHA_AMP_OUT_N (out, see 9), CHA_AMP_OUT_P (out, see 9), CHB_AMP_OUT_N (out, see 9), CHB_AMP_OUT_P (out, see 9), VCM_AMP (in, see 9, 10)

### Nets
3p9V_LMH: C126.2 C127.2 C128.2 C129.2 C145.2 C146.2 C147.2 C148.2 R151.2 R153.2 R170.2 R172.2 U21.1(VS+) U21.10(VS+) U22.5(VCC) U23.1(VS+) U23.10(VS+) U24.5(VCC)
-1p1V_LMH: C130.2 C131.2 C132.2 C133.2 C149.2 C150.2 C151.2 C152.2 U21.3(VS-) U21.8(VS-) U22.2(GND) U23.3(VS-) U23.8(VS-) U24.2(GND)
GND: C126.1 C127.1 C128.1 C129.1 C130.1 C131.1 C132.1 C133.1 C135.1 C138.2 C140.1 C142.2 C144.1 C145.1 C146.1 C147.1 C148.1 C149.1 C150.1 C151.1 C152.1 C154.1 C157.2 C159.2 C161.2 C163.1 J4.2 J4.3 J4.4 J4.5 J5.2 J5.3 J5.4 J5.5 J7.2 J7.3 J7.4 J7.5 J8.2 J8.3 J8.4 J8.5 R144.1 R146.1 R152.1 R157.1 R163.1 R165.2 R171.1 R176.1 U21.11(GND) U21.14(GND) U23.11(GND) U23.14(GND)
CHA_AMP_OUT_N: C135.2 L6.2 ; port CHA_AMP_OUT_N
CHA_AMP_OUT_P: C138.1 L8.2 ; port CHA_AMP_OUT_P
CHB_AMP_OUT_N: C154.2 L10.2 ; port CHB_AMP_OUT_N
CHB_AMP_OUT_P: C157.1 L12.2 ; port CHB_AMP_OUT_P
VCM_AMP: C144.2 C163.2 U22.1(IN+) U24.1(IN+) ; port VCM_AMP
NetC134_1: C134.1 R140.2 R144.2
NetC134_2: C134.2 R141.1
NetC136_1: C136.1 L7.1 R145.1 R150.2 R154.2
NetC136_2: C136.2 L5.1 R143.2 R145.2 R155.2
NetC137_1: C137.1 L7.2 L8.1
NetC137_2: C137.2 L5.2 L6.1
NetC139_1: C139.1 R146.2 R147.2
NetC139_2: C139.2 R148.1
NetC140_2: C140.2 R151.1 R152.2 R158.1 U21.2(CM)
NetC141_1: C141.1 R156.1 U22.3(IN-)
NetC141_2: C141.2 R158.2 U22.4(Y)
NetC142_1: C142.1 R154.1 R155.1 R156.2
NetC153_1: C153.1 R159.2 R163.2
NetC153_2: C153.2 R160.1
NetC155_1: C155.1 L11.1 R164.1 R169.2 R173.2
NetC155_2: C155.2 L9.1 R162.2 R164.2 R174.2
NetC156_1: C156.1 L11.2 L12.1
NetC156_2: C156.2 L9.2 L10.1
NetC158_1: C158.1 R167.1
NetC158_2: C158.2 R165.1 R166.2
NetC159_1: C159.1 R170.1 R171.2 R177.1 U23.2(CM)
NetC160_1: C160.1 R175.1 U24.3(IN-)
NetC160_2: C160.2 R177.2 U24.4(Y)
NetC161_1: C161.1 R173.1 R174.1 R175.2
NetJ4_1: J4.1 R147.1
NetJ5_1: J5.1 R140.1
NetJ7_1: J7.1 R166.1
NetJ8_1: J8.1 R159.1
NetR141_2: R141.2 R142.1 U21.6(IN+)
NetR142_2: R142.2 U21.7(FB-)
NetR143_1: R143.1 U21.13(OUT+)
NetR148_2: R148.2 R149.1 U21.5(IN-)
NetR149_2: R149.2 U21.4(FB+)
NetR150_1: R150.1 U21.12(OUT-)
NetR153_1: R153.1 R157.2 U21.9(PD)
NetR160_2: R160.2 R161.1 U23.6(IN+)
NetR161_2: R161.2 U23.7(FB-)
NetR162_1: R162.1 U23.13(OUT+)
NetR167_2: R167.2 R168.1 U23.5(IN-)
NetR168_2: R168.2 U23.4(FB+)
NetR169_1: R169.1 U23.12(OUT-)
NetR172_1: R172.1 R176.2 U23.9(PD)

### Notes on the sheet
- Amplifier
- Refer to LMH5401 Datasheet for other configurations
- (DC/AC coupled, Single Ended/Differential)
- Single Ended to Differential configuration by default
- These Ls are placeholders, which are populated with 0Ω

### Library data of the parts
C126 C127 C130 C131 C140 C144-C146 C149 C150 C159 C163 = capcc05522: CAP CER 10000PF 10V X7R 0201; Manufacturer: TDK Corporation; CompType: Capacitor Ceramic; Tolerance: ±10%; SizeX_mm: 0.6; SizeY_mm: 0.3; SizeZ_mm: 0.33
C128 C129 C132 C133 C147 C148 C151 C152 = capcc04220: CAP CER 2200PF 10V X7R 0201; Manufacturer: KYOCERA AVX; CompType: Capacitor Ceramic; Tolerance: ±10%; SizeX_mm: 0.6; SizeY_mm: 0.3; SizeZ_mm: 0.33
C134 C139 C153 C158 = capcc09263: as C92 on sheet ADC Analog Input
C135 C138 C154 C157 = 0201RFCaps0065: CAP CER 2PF 25V C0G/NP0 0201; Manufacturer: Murata Electronics; CompType: Capactior RF; Tolerance: ±0.05pF; Temperature Coefficient: C0G, NP0; SizeX_mm: 0.6; SizeY_mm: 0.3; SizeZ_mm: 0.33
C136 C155 = 0201RFCaps0260: CAP CER 0.7PF 25V C0G/NP0 0201; Manufacturer: Murata Electronics; CompType: Capactior RF; Tolerance: ±0.1pF; Temperature Coefficient: C0G, NP0; SizeX_mm: 0.6; SizeY_mm: 0.3; SizeZ_mm: 0.33
C137 C156 = 0201RFCaps0405: CAP CER 6.6PF 25V NP0 0201; Manufacturer: Murata Electronics; CompType: Capactior RF; Tolerance: ±0.25pF; Temperature Coefficient: C0G, NP0; SizeX_mm: 0.6; SizeY_mm: 0.3; SizeZ_mm: 0.33
C141 C142 C160 C161 = capcc02750: as C80 on sheet ADC IO
J4 J5 J7 J8 = 132134-15: SMA Connector Jack, Female Socket 50Ohm Surface Mount, Through Hole Solder; Manufacturer: Amphenol RF; CompType: RF Connector; UniqueID: cmp00028
L5 L7 L9 L11 = indrf00014: RF Ceramic Chip Inductors; Manufacturer: Coilcraft; CompType: Inductor RF; Tolerance: ±5%; Current Rating: 260 mA; DC Resistance (DCR): 370 mΩ; Frequency - Self Resonant: 6.25 GHz; SizeX_mm: 0.76; SizeY_mm: 0.33; SizeZ_mm: 0.55
L6 L8 L10 L12 = indrf00011: RF Ceramic Chip Inductors; Manufacturer: Coilcraft; CompType: Inductor RF; Tolerance: ±5%; Current Rating: 440 mA; DC Resistance (DCR): 155 mΩ; Frequency - Self Resonant: 8 GHz; SizeX_mm: 0.76; SizeY_mm: 0.33; SizeZ_mm: 0.55
R140 R146 R147 R159 R165 R166 = RSMD020101699: as R82-R109 on sheet ADC IO
R141 R158 R160 R177 = RSMD020100324: RES 22.6 OHM 1% 1/20W 0201 SMD; Manufacturer: Panasonic Electronic Components; CompType: Resistor SMD; Power (Watts): 0.05W, 1/20W; Temperature Coefficient: ±200ppm/°C
R142 R149 R161 R168 = RSMD020100228: RES SMD 127 OHM 1% 1/20W 0201; Manufacturer: Panasonic Electronic Components; CompType: Resistor SMD; Power (Watts): 0.05W, 1/20W; Temperature Coefficient: ±200ppm/°C
R143 R150 R162 R169 = RSMD020100033: RES SMD 40.2 OHM 1% 1/20W 0201; Manufacturer: Panasonic Electronic Components; CompType: Resistor SMD; Power (Watts): 0.05W, 1/20W; Temperature Coefficient: ±200ppm/°C
R144 R163 = RSMD020100044: RES SMD 357 OHM 1% 1/20W 0201; Manufacturer: Panasonic Electronic Components; CompType: Resistor SMD; Power (Watts): 0.05W, 1/20W; Temperature Coefficient: ±200ppm/°C
R145 R156 R164 R175 = RSMD020100735: RES 10K OHM 1% 1/20W 0201 SMD; Manufacturer: Panasonic Electronic Components; CompType: Resistor SMD; Power (Watts): 0.05W, 1/20W; Temperature Coefficient: ±200ppm/°C
R148 R167 = RSMD020100281: RES SMD 66.5 OHM 1% 1/20W 0201; Manufacturer: Panasonic Electronic Components; CompType: Resistor SMD; Power (Watts): 0.05W, 1/20W; Temperature Coefficient: ±200ppm/°C
R151 R170 = RSMD040200008: RES SMD 1K OHM 5% 1/10W 0402; Manufacturer: Panasonic Electronic Components; CompType: Resistor SMD; Power (Watts): 0.1W, 1/10W; Temperature Coefficient: ±200ppm/°C; SizeX_mm: 1; SizeY_mm: 0.5; SizeZ_mm: 0.4
R152 R171 = RSMD040203233: RES SMD 590 OHM 1% 1/10W 0402; Manufacturer: Panasonic Electronic Components; CompType: Resistor SMD; Power (Watts): 0.1W, 1/10W; Temperature Coefficient: ±100ppm/°C; SizeX_mm: 1; SizeY_mm: 0.5; SizeZ_mm: 0.4
R153 R172 = RSMD040200314: as R125 on sheet ADC IO
R154 R155 R173 R174 = RSMD020100261: RES 1.5K OHM 1% 1/20W 0201 SMD; Manufacturer: Panasonic Electronic Components; CompType: Resistor SMD; Power (Watts): 0.05W, 1/20W; Temperature Coefficient: ±200ppm/°C
R157 R176 = RSMD040200311: as R112 on sheet ADC IO
U21 U23 = LMH5401IRMSR: 8GHz Ultra Wideband Fully Differential Amplifier, RMS0014A (UQFN-14); Manufacturer: Texas Instruments; Alternate PartNumber: LMH5401IRMST; SymbolCreator: Altium; Green_Lifecycle: Active; Rating: Catalog; AEC Category: Q200; SizeX_mm: 2.5; AEC Qualified: N; CompType: IC; SizeArea_mm2: 6.25; SizeAreaWB_mm2: 12.25; Green_REACh: Passed; SizeZ_mm: 0.6
U22 U24 = OPA376AIDCKR: Manufacturer: Texas Instruments

## Sheet FMC Sections 1-7 .SchDoc: FMC Section Rows A - E
size 431 x 279 mm; Date: Not shown in title block; ApprovedBy: Not shown in title block; CheckedBy: Not shown in title block; Author: Not shown in title block; CompanyName: Not shown in title block; Engineer: Not shown in title block; Organization: Not shown in title block; Address1: Not shown in title block; Address2: Not shown in title block; Address3: Not shown in title block; Address4: Not shown in title block; DocumentNumber: 2; Revision: Use project parameter SCH_Rev; SheetNumber: 11; SheetTotal: 17; PageSetup: Record=PageOptions¦CenterHorizontal=True¦CenterVertical=True¦PrintScale=1.00¦XCorrection=1.00¦YCorrection=1.00¦PrintKind=0¦BorderSize=5000000¦LeftOffset=0¦BottomOffset=0¦Orientation=2¦PaperLength=1000¦PaperWidth=1000¦Scale=100¦PaperSource=15¦PrintQuality=600¦MediaType=1¦DitherType=10¦PaperKind=Letter¦PrintScaleMode=1
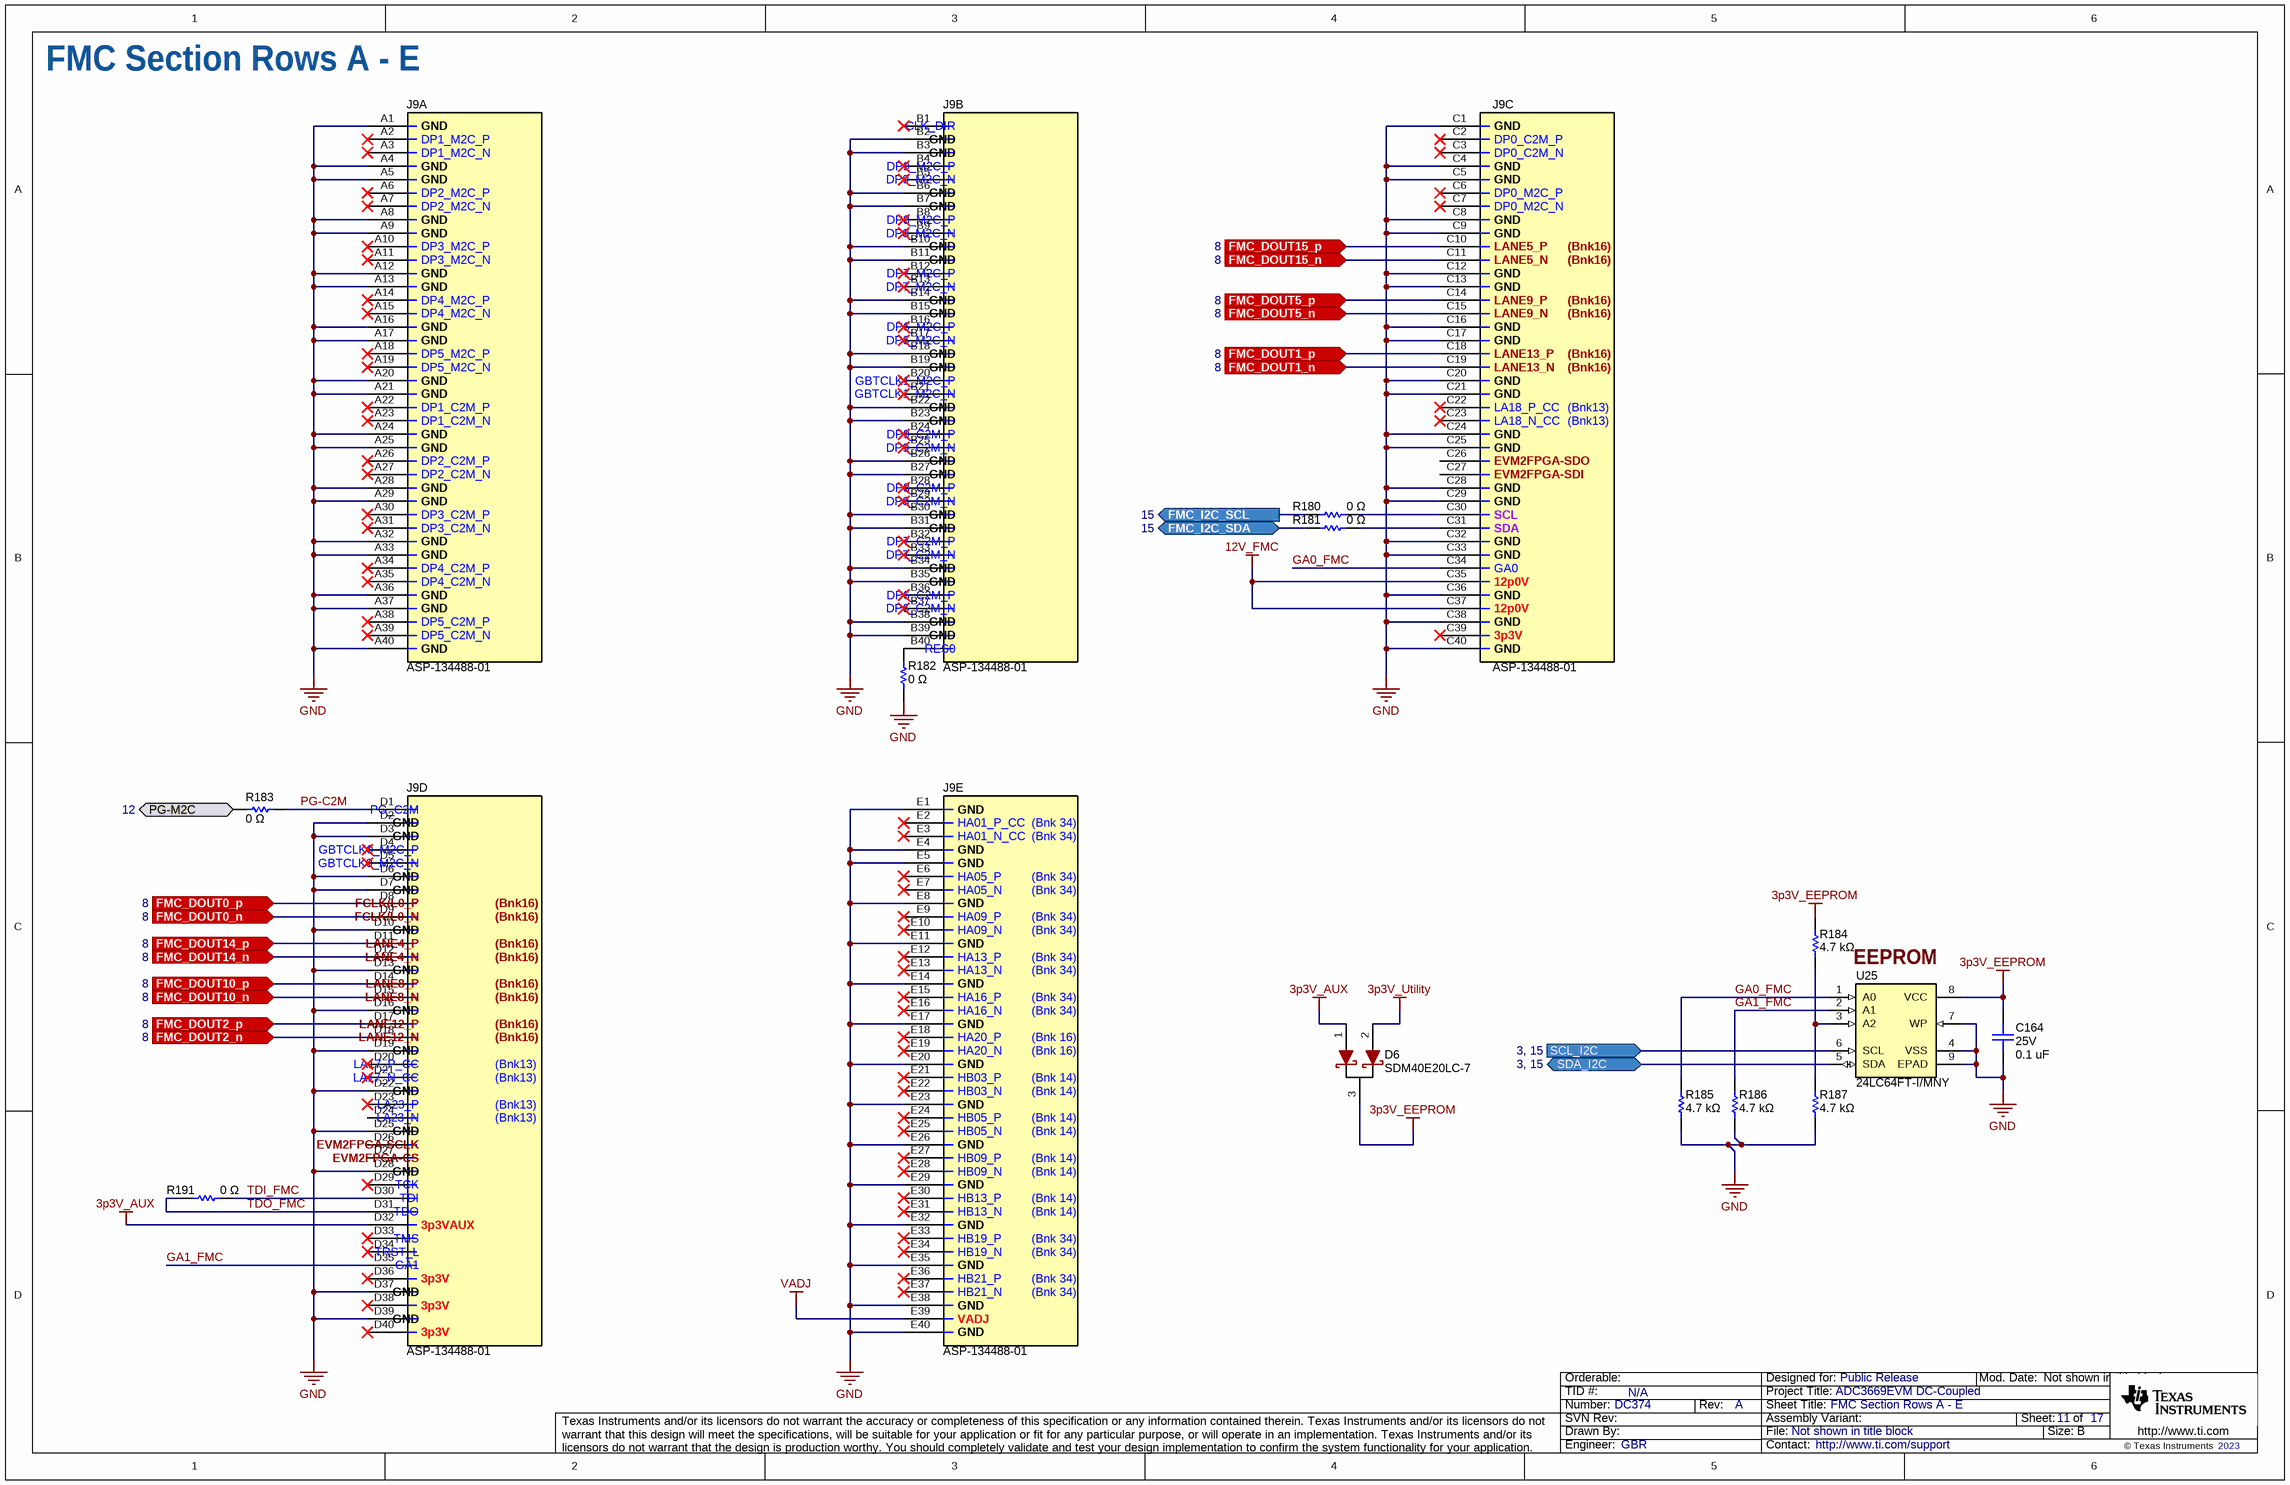
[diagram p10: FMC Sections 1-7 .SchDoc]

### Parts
C164  value 0.1 uF  Voltage - Rated: 25V  [0402L_cap]  (hidden comment: C1005X5R1E104K050BC)
D6  SDM40E20LC-7  [SOT-323-DIO]
J9  ASP-134488-01  [SAMTEC_ASP-134488-01]  (parts A,B,C,D,E of 10)
R180  value 0 Ω  [0402L]  (hidden comment: ERJ-2GE0R00X)
R181  value 0 Ω  [0402L]  (hidden comment: ERJ-2GE0R00X)
R182  value 0 Ω  [0603L]  (hidden comment: ERJ-3GEY0R00V)
R183  value 0 Ω  [0603L]  (hidden comment: ERJ-3GEY0R00V)
R184  value 4.7 kΩ  [0402L]  (hidden comment: ERJ-2GEJ472X)
R185  value 4.7 kΩ  [0402L]  (hidden comment: ERJ-H2RF4701X)
R186  value 4.7 kΩ  [0402L]  (hidden comment: ERJ-H2RF4701X)
R187  value 4.7 kΩ  [0402L]  (hidden comment: ERJ-H2RF4701X)
R191  value 0 Ω  [0402L]  (hidden comment: ERJ-2GE0R00X)
U25  24LC64FT-I/MNY  [TDFN8]

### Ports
FMC_DOUT0_n (in, see 8), FMC_DOUT0_p (in, see 8), FMC_DOUT1_n (in, see 8), FMC_DOUT1_p (in, see 8), FMC_DOUT2_n (in, see 8), FMC_DOUT2_p (in, see 8), FMC_DOUT5_n (in, see 8), FMC_DOUT5_p (in, see 8), FMC_DOUT10_n (in, see 8), FMC_DOUT10_p (in, see 8), FMC_DOUT14_n (in, see 8), FMC_DOUT14_p (in, see 8), FMC_DOUT15_n (in, see 8), FMC_DOUT15_p (in, see 8), FMC_I2C_SCL (out, see 15), FMC_I2C_SDA (bidir, see 15), PG-M2C (bidir, see 12), SCL_I2C (in, see 3, 15), SDA_I2C (bidir, see 3, 15)

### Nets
3p3V_AUX: D6.1(K) J9.D32
3p3V_EEPROM: C164.2 D6.3(A) R184.2 U25.8(VCC)
3p3V_Utility: D6.2(A)
12V_FMC: J9.C35 J9.C37
GND: C164.1 J9.A1 J9.A4 J9.A5 J9.A8 J9.A9 J9.A12 J9.A13 J9.A16 J9.A17 J9.A20 J9.A21 J9.A24 J9.A25 J9.A28 J9.A29 J9.A32 J9.A33 J9.A36 J9.A37 J9.A40 J9.B2 J9.B3 J9.B6 J9.B7 J9.B10 J9.B11 J9.B14 J9.B15 J9.B18 J9.B19 J9.B22 J9.B23 J9.B26 J9.B27 J9.B30 J9.B31 J9.B34 J9.B35 J9.B38 J9.B39 J9.C1 J9.C4 J9.C5 J9.C8 J9.C9 J9.C12 J9.C13 J9.C16 J9.C17 J9.C20 J9.C21 J9.C24 J9.C25 J9.C28 J9.C29 J9.C32 J9.C33 J9.C36 J9.C38 J9.C40 J9.D2 J9.D3 J9.D6 J9.D7 J9.D10 J9.D13 J9.D16 J9.D19 J9.D22 J9.D25 J9.D28 J9.D37 J9.D39 J9.E1 J9.E4 J9.E5 J9.E8 J9.E11 J9.E14 J9.E17 J9.E20 J9.E23 J9.E26 J9.E29 J9.E32 J9.E35 J9.E38 J9.E40 R182.1 R185.1 R186.1 R187.1 U25.4(VSS) U25.7(WP) U25.9(EPAD)
VADJ: J9.E39
FMC_DOUT0_n: J9.D9 ; port FMC_DOUT0_n
FMC_DOUT0_p: J9.D8 ; port FMC_DOUT0_p
FMC_DOUT1_n: J9.C19 ; port FMC_DOUT1_n
FMC_DOUT1_p: J9.C18 ; port FMC_DOUT1_p
FMC_DOUT2_n: J9.D18 ; port FMC_DOUT2_n
FMC_DOUT2_p: J9.D17 ; port FMC_DOUT2_p
FMC_DOUT5_n: J9.C15 ; port FMC_DOUT5_n
FMC_DOUT5_p: J9.C14 ; port FMC_DOUT5_p
FMC_DOUT10_n: J9.D15 ; port FMC_DOUT10_n
FMC_DOUT10_p: J9.D14 ; port FMC_DOUT10_p
FMC_DOUT14_n: J9.D12 ; port FMC_DOUT14_n
FMC_DOUT14_p: J9.D11 ; port FMC_DOUT14_p
FMC_DOUT15_n: J9.C11 ; port FMC_DOUT15_n
FMC_DOUT15_p: J9.C10 ; port FMC_DOUT15_p
FMC_I2C_SCL: R180.1 ; port FMC_I2C_SCL
FMC_I2C_SDA: R181.1 ; port FMC_I2C_SDA
GA0_FMC: J9.C34 R185.2 U25.1(A0)
GA1_FMC: J9.D35 R186.2 U25.2(A1)
PG-C2M: J9.D1 R183.1
PG-M2C: R183.2 ; port PG-M2C
SCL_I2C: U25.6(SCL) ; port SCL_I2C
SDA_I2C: U25.5(SDA) ; port SDA_I2C
TDI_FMC: J9.D30 R191.2
TDO_FMC: J9.D31 R191.1
NetJ9_B40: J9.B40 R182.2
NetJ9_C30: J9.C30 R180.2
NetJ9_C31: J9.C31 R181.2
NetR184_1: R184.1 R187.2 U25.3(A2)

Not connected (* = marked no-connect by the designer): J9 A2* A3* A6* A7* A10* A11* A14* A15* A18* A19* A22* A23* A26* A27* A30* A31* A34* A35* A38* A39* B1* B4* B5* B8* B9* B12* B13* B16* B17* B20* B21* B24* B25* B28* B29* B32* B33* B36* B37* C2* C3* C6* C7* C22* C23* C26 C27 C39* D4* D5* D20* D21* D23* D24 D26 D27 D29* D33* D34* D36* D38* D40* E2* E3* E6* E7* E9* E10* E12* E13* E15* E16* E18* E19* E21* E22* E24* E25* E27* E28* E30* E31* E33* E34* E36* E37*

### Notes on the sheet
- (near U25) EEPROM

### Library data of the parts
C164 = capcc01263: as C81 on sheet ADC IO
D6 = SDM40E20LC-7: Diode Array 1 Pair Common Cathode 20 V 400mA (DC); Manufacturer: Diodes Inc; Text1: 310mV@100mA
J9 = ASP-134488-01: FMC, High Density Array, Male / EVM Connector 40x10; Manufacturer: Samtec; UniqueID: cmp00010; Pitch (mm): 1.27
R180 R181 R191 = RSMD040200001: RES SMD 0 OHM JUMPER 1/10W 0402; Manufacturer: Panasonic Electronic Components; Power (Watts): 0.1W, 1/10W; CompType: Resistor SMD; SizeX_mm: 1; SizeY_mm: 0.5; SizeZ_mm: 0.4
R182 R183 = RSMD060312289: RES SMD 0 OHM JUMPER 1/10W 0603; Manufacturer: Panasonic Electronic Components; Power (Watts): 0.1W, 1/10W; SizeX_mm: 1.6; SizeY_mm: 0.8; SizeZ_mm: 0.55; CompType: Resistor SMD
R184 = RSMD040202585: RES SMD 4.7K OHM 5% 1/10W 0402; Manufacturer: Panasonic Electronic Components; CompType: Resistor SMD; Power (Watts): 0.1W, 1/10W; Temperature Coefficient: ±200ppm/°C; SizeX_mm: 1; SizeY_mm: 0.5; SizeZ_mm: 0.4
R185-R187 = RSMD040202592: RES 4.7K OHM 1% 1/10W 0402; Manufacturer: Panasonic Electronic Components; CompType: Resistor SMD; Power (Watts): 0.1W, 1/10W; Temperature Coefficient: ±100ppm/°C; SizeX_mm: 1; SizeY_mm: 0.5; SizeZ_mm: 0.4
U25 = cmp00154: EEPROM 64K 8KX8 1.8V SER EE IND 1/4AWP RPO; Manufacturer: Microchip

## Sheet FMC Sections 8-14.SchDoc: FMC Section Rows F - H, J, K
size 431 x 279 mm; Date: Not shown in title block; ApprovedBy: Not shown in title block; CheckedBy: Not shown in title block; Author: Not shown in title block; CompanyName: Not shown in title block; Engineer: Not shown in title block; Organization: Not shown in title block; Address1: Not shown in title block; Address2: Not shown in title block; Address3: Not shown in title block; Address4: Not shown in title block; DocumentNumber: 3; Revision: Use project parameter SCH_Rev; SheetNumber: 12; SheetTotal: 17; PageSetup: Record=PageOptions¦CenterHorizontal=True¦CenterVertical=True¦PrintScale=1.00¦XCorrection=1.00¦YCorrection=1.00¦PrintKind=0¦BorderSize=5000000¦LeftOffset=0¦BottomOffset=0¦Orientation=2¦PaperLength=1000¦PaperWidth=1000¦Scale=100¦PaperSource=15¦PrintQuality=600¦MediaType=1¦DitherType=10¦PaperKind=Letter¦PrintScaleMode=1
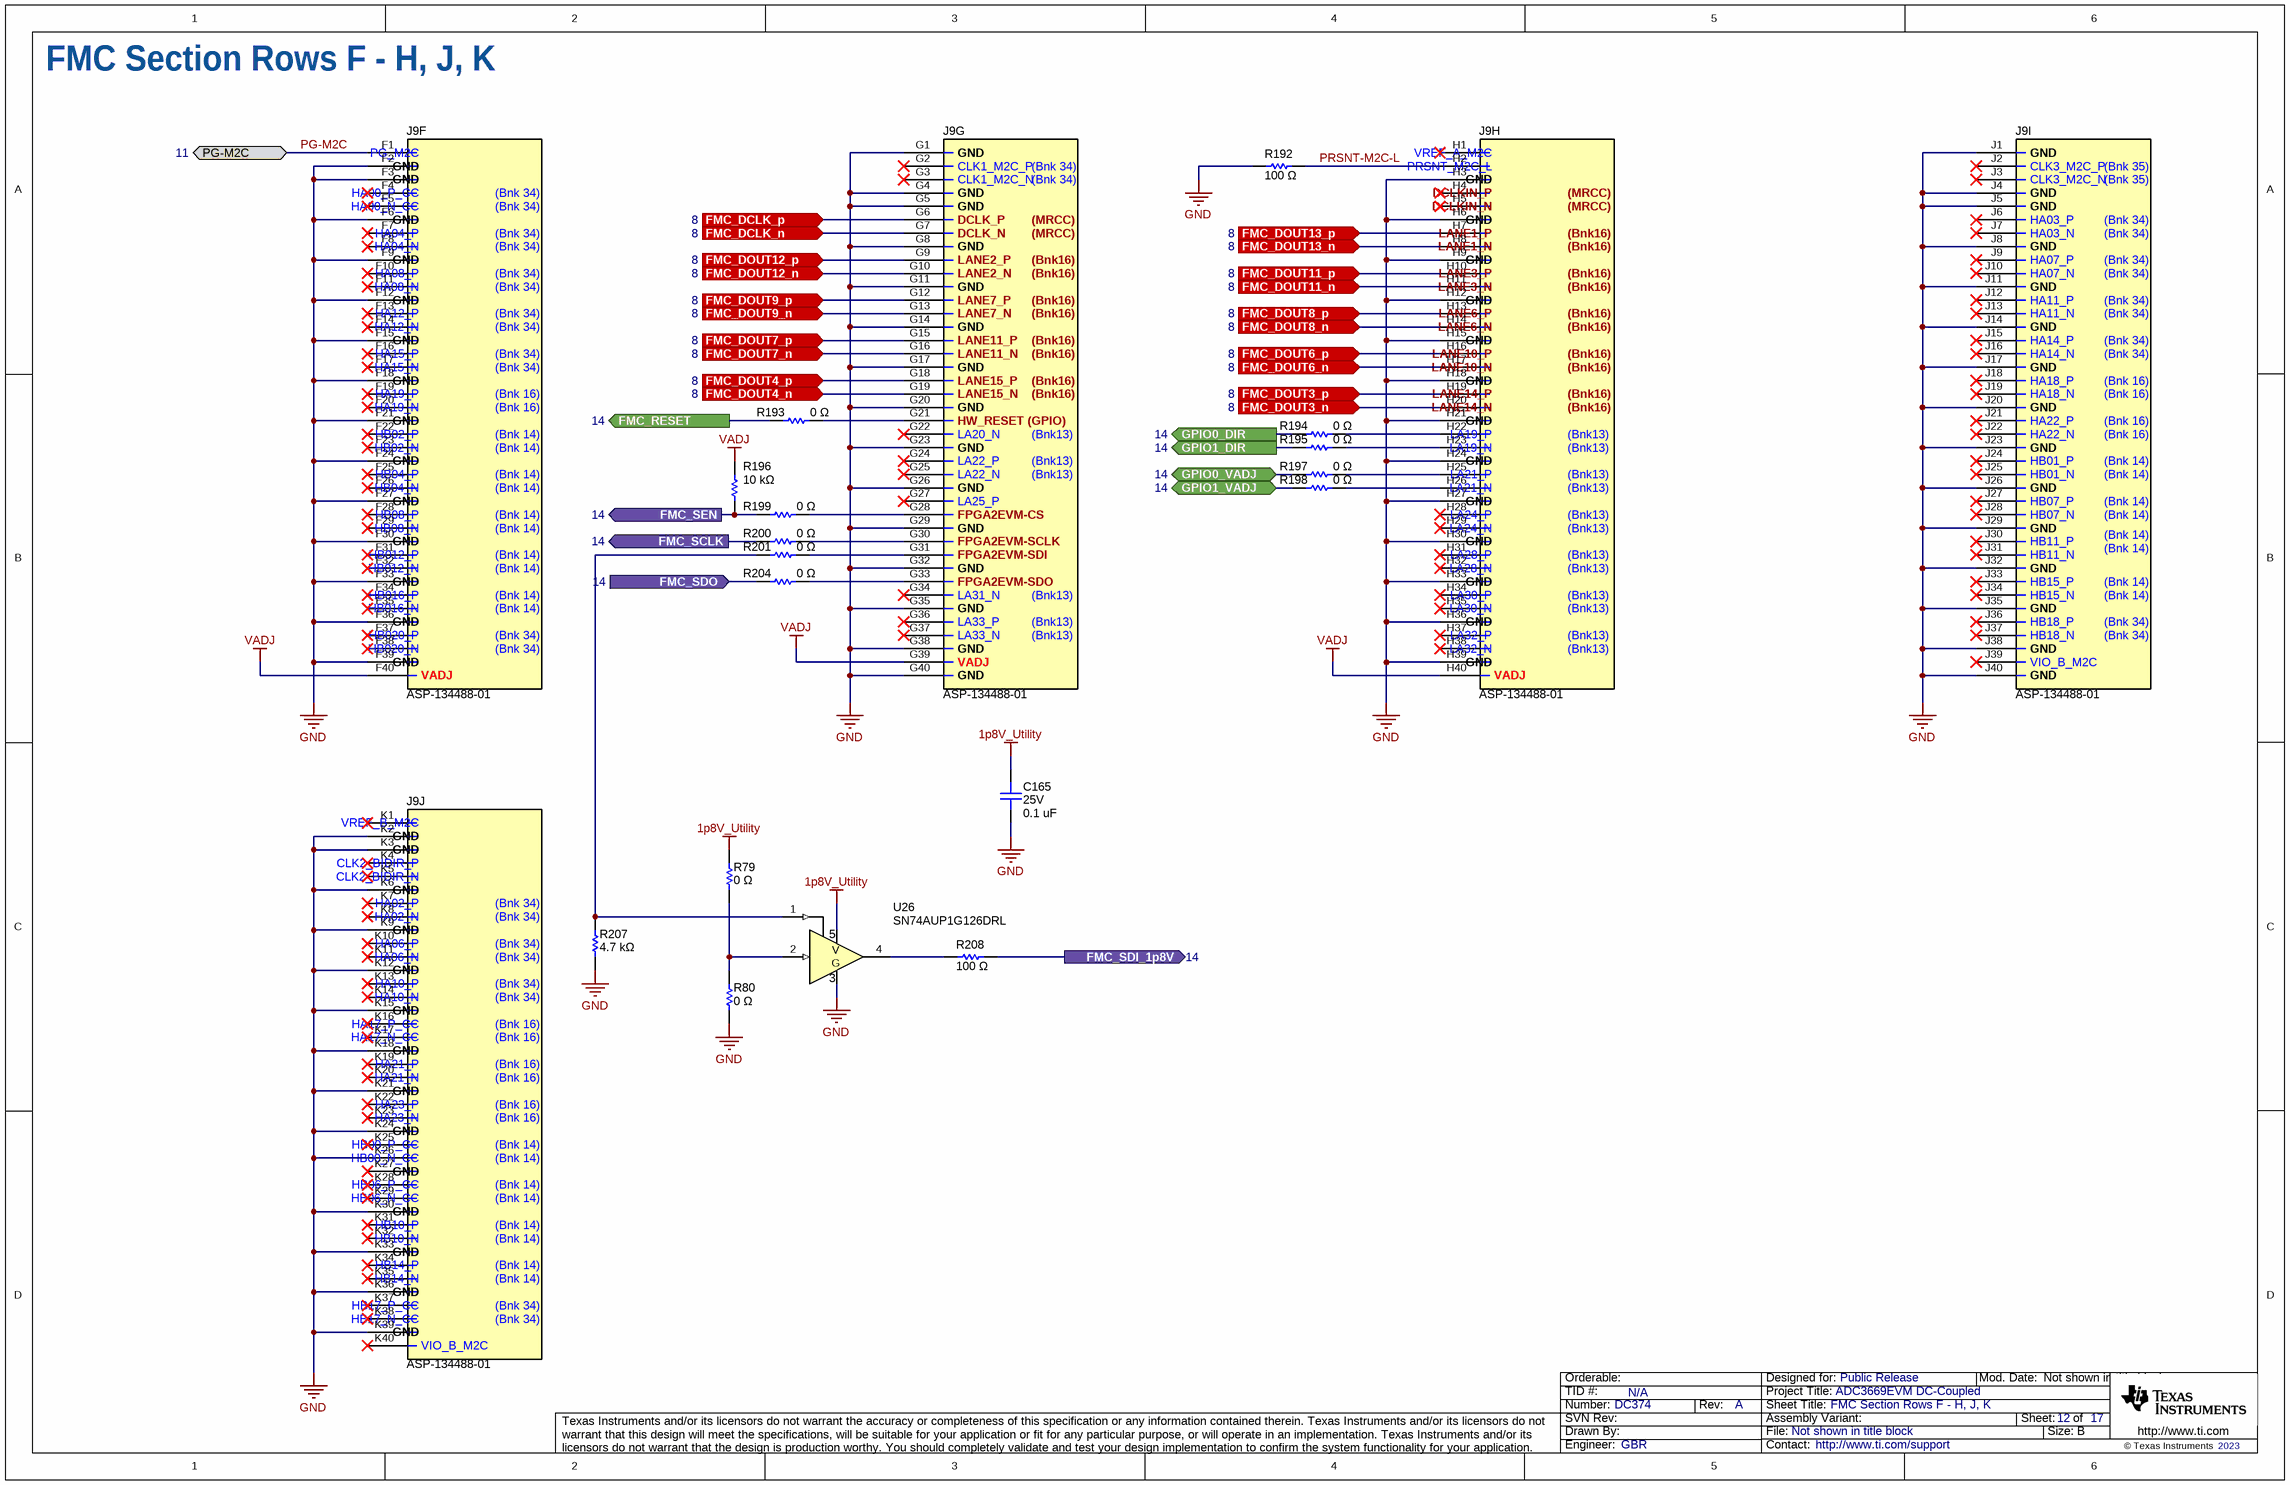
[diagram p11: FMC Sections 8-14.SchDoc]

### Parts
C165  value 0.1 uF  Voltage - Rated: 25V  [0402L_cap]  (hidden comment: C1005X5R1E104K050BC)
J9  ASP-134488-01  [SAMTEC_ASP-134488-01]  (parts F,G,H,I,J of 10)
R79  value 0 Ω  [0402L]  (hidden comment: ERJ-2GE0R00X)
R80  value 0 Ω  [0402L]  (hidden comment: ERJ-2GE0R00X)
R192  value 100 Ω  [0603L]  (hidden comment: ERJ-H3GJ101V)
R193  value 0 Ω  [0402L]  (hidden comment: ERJ-2GE0R00X)
R194  value 0 Ω  [0402L]  (hidden comment: ERJ-2GE0R00X)
R195  value 0 Ω  [0402L]  (hidden comment: ERJ-2GE0R00X)
R196  value 10 kΩ  [0402L]  (hidden comment: ERJ-2RKF1002X)
R197  value 0 Ω  [0402L]  (hidden comment: ERJ-2GE0R00X)
R198  value 0 Ω  [0402L]  (hidden comment: ERJ-2GE0R00X)
R199  value 0 Ω  [0402L]  (hidden comment: ERJ-2GE0R00X)
R200  value 0 Ω  [0402L]  (hidden comment: ERJ-2GE0R00X)
R201  value 0 Ω  [0402L]  (hidden comment: ERJ-2GE0R00X)
R204  value 0 Ω  [0402L]  (hidden comment: ERJ-2GE0R00X)
R207  value 4.7 kΩ  [0402L]  (hidden comment: ERJ-H2RF4701X)
R208  value 100 Ω  [0402L]  (hidden comment: ERJ-H2RF1000X)
U26  SN74AUP1G126DRL  [DRL0005A]

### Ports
FMC_DCLK_n (in, see 8), FMC_DCLK_p (in, see 8), FMC_DOUT3_n (in, see 8), FMC_DOUT3_p (in, see 8), FMC_DOUT4_n (in, see 8), FMC_DOUT4_p (in, see 8), FMC_DOUT6_n (in, see 8), FMC_DOUT6_p (in, see 8), FMC_DOUT7_n (in, see 8), FMC_DOUT7_p (in, see 8), FMC_DOUT8_n (in, see 8), FMC_DOUT8_p (in, see 8), FMC_DOUT9_n (in, see 8), FMC_DOUT9_p (in, see 8), FMC_DOUT11_n (in, see 8), FMC_DOUT11_p (in, see 8), FMC_DOUT12_n (in, see 8), FMC_DOUT12_p (in, see 8), FMC_DOUT13_n (in, see 8), FMC_DOUT13_p (in, see 8), FMC_RESET (out, see 14), FMC_SCLK (out, see 14), FMC_SDI_1p8V (out, see 14), FMC_SDO (in, see 14), FMC_SEN (out, see 14), GPIO0_DIR (out, see 14), GPIO0_VADJ (bidir, see 14), GPIO1_DIR (out, see 14), GPIO1_VADJ (bidir, see 14), PG-M2C (bidir, see 11)

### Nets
1p8V_Utility: C165.2 R79.2 U26.5(VCC)
GND: C165.1 J9.F2 J9.F3 J9.F6 J9.F9 J9.F12 J9.F15 J9.F18 J9.F21 J9.F24 J9.F27 J9.F30 J9.F33 J9.F36 J9.F39 J9.G1 J9.G4 J9.G5 J9.G8 J9.G11 J9.G14 J9.G17 J9.G20 J9.G23 J9.G26 J9.G29 J9.G32 J9.G35 J9.G38 J9.G40 J9.H3 J9.H6 J9.H9 J9.H12 J9.H15 J9.H18 J9.H21 J9.H24 J9.H27 J9.H30 J9.H33 J9.H36 J9.H39 J9.J1 J9.J4 J9.J5 J9.J8 J9.J11 J9.J14 J9.J17 J9.J20 J9.J23 J9.J26 J9.J29 J9.J32 J9.J35 J9.J38 J9.J40 J9.K2 J9.K3 J9.K6 J9.K9 J9.K12 J9.K15 J9.K18 J9.K21 J9.K24 J9.K26 J9.K30 J9.K33 J9.K36 J9.K39 R80.1 R192.1 R207.1 U26.3(GND)
VADJ: J9.F40 J9.G39 J9.H40 R196.2
FMC_DCLK_n: J9.G7 ; port FMC_DCLK_n
FMC_DCLK_p: J9.G6 ; port FMC_DCLK_p
FMC_DOUT3_n: J9.H20 ; port FMC_DOUT3_n
FMC_DOUT3_p: J9.H19 ; port FMC_DOUT3_p
FMC_DOUT4_n: J9.G19 ; port FMC_DOUT4_n
FMC_DOUT4_p: J9.G18 ; port FMC_DOUT4_p
FMC_DOUT6_n: J9.H17 ; port FMC_DOUT6_n
FMC_DOUT6_p: J9.H16 ; port FMC_DOUT6_p
FMC_DOUT7_n: J9.G16 ; port FMC_DOUT7_n
FMC_DOUT7_p: J9.G15 ; port FMC_DOUT7_p
FMC_DOUT8_n: J9.H14 ; port FMC_DOUT8_n
FMC_DOUT8_p: J9.H13 ; port FMC_DOUT8_p
FMC_DOUT9_n: J9.G13 ; port FMC_DOUT9_n
FMC_DOUT9_p: J9.G12 ; port FMC_DOUT9_p
FMC_DOUT11_n: J9.H11 ; port FMC_DOUT11_n
FMC_DOUT11_p: J9.H10 ; port FMC_DOUT11_p
FMC_DOUT12_n: J9.G10 ; port FMC_DOUT12_n
FMC_DOUT12_p: J9.G9 ; port FMC_DOUT12_p
FMC_DOUT13_n: J9.H8 ; port FMC_DOUT13_n
FMC_DOUT13_p: J9.H7 ; port FMC_DOUT13_p
FMC_RESET: R193.1 ; port FMC_RESET
FMC_SCLK: R200.1 ; port FMC_SCLK
FMC_SDI_1p8V: R208.2 ; port FMC_SDI_1p8V
FMC_SDO: R204.1 ; port FMC_SDO
FMC_SEN: R196.1 R199.1 ; port FMC_SEN
GPIO0_DIR: R194.1 ; port GPIO0_DIR
GPIO0_VADJ: R197.1 ; port GPIO0_VADJ
GPIO1_DIR: R195.1 ; port GPIO1_DIR
GPIO1_VADJ: R198.1 ; port GPIO1_VADJ
PG-M2C: J9.F1 ; port PG-M2C
PRSNT-M2C-L: J9.H2 R192.2
NetJ9_G21: J9.G21 R193.2
NetJ9_G28: J9.G28 R199.2
NetJ9_G30: J9.G30 R200.2
NetJ9_G31: J9.G31 R201.2
NetJ9_G33: J9.G33 R204.2
NetJ9_H22: J9.H22 R194.2
NetJ9_H23: J9.H23 R195.2
NetJ9_H25: J9.H25 R197.2
NetJ9_H26: J9.H26 R198.2
NetR79_1: R79.1 R80.2 U26.2(A)
NetR201_1: R201.1 R207.2 U26.1(~{OE})
NetR208_1: R208.1 U26.4(Y)

Not connected (* = marked no-connect by the designer): J9 F4* F5* F7* F8* F10* F11* F13* F14* F16* F17* F19* F20* F22* F23* F25* F26* F28* F29* F31* F32* F34* F35* F37* F38* G2* G3* G22* G24* G25* G27* G34* G36* G37* H1* H4* H5* H28* H29* H31* H32* H34* H35* H37* H38* J2* J3* J6* J7* J9* J10* J12* J13* J15* J16* J18* J19* J21* J22* J24* J25* J27* J28* J30* J31* J33* J34* J36* J37* J39* K1* K4* K5* K7* K8* K10* K11* K13* K14* K16* K17* K19* K20* K22* K23* K25* K27* K28* K29* K31* K32* K34* K35* K37* K38* K40*

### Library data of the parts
C165 = capcc01263: as C81 on sheet ADC IO
J9 = ASP-134488-01: as J9 on sheet FMC Sections 1-7 
R79 R80 = RSMD040200001: as R111 on sheet ADC IO
R192 = RSMD060309678: RES 100 OHM 5% 1/8W 0603; Manufacturer: Panasonic Electronic Components; Power (Watts): 0.125W, 1/8W; Temperature Coefficient: ±200ppm/°C; SizeX_mm: 1.6; SizeY_mm: 0.8; SizeZ_mm: 0.55
R193-R195 R197-R201 R204 = RSMD040200001: as R180 on sheet FMC Sections 1-7 
R196 = RSMD040200314: as R125 on sheet ADC IO
R207 = RSMD040202592: as R185-R187 on sheet FMC Sections 1-7 
R208 = RSMD040200378: RES 100 OHM 1% 1/10W 0402; Manufacturer: Panasonic Electronic Components; CompType: Resistor SMD; Power (Watts): 0.1W, 1/10W; Temperature Coefficient: ±100ppm/°C; SizeX_mm: 1; SizeY_mm: 0.5; SizeZ_mm: 0.4
U26 = SN74AUP1G126DRL: 0.8V→3.6V Single Bus Buffer Gate With 3-State Outputs. Active high enable.; Manufacturer: Texas Instruments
